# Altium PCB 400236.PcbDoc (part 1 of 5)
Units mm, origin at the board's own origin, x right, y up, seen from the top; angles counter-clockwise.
Board outline 136.53 x 63.5 mm, 4 copper layers (Top Layer, Mid-Layer 1, Mid-Layer 2, Bottom Layer), stack 1.505 mm thick; 340 components, 230 nets, 1369 pads, 1292 vias.
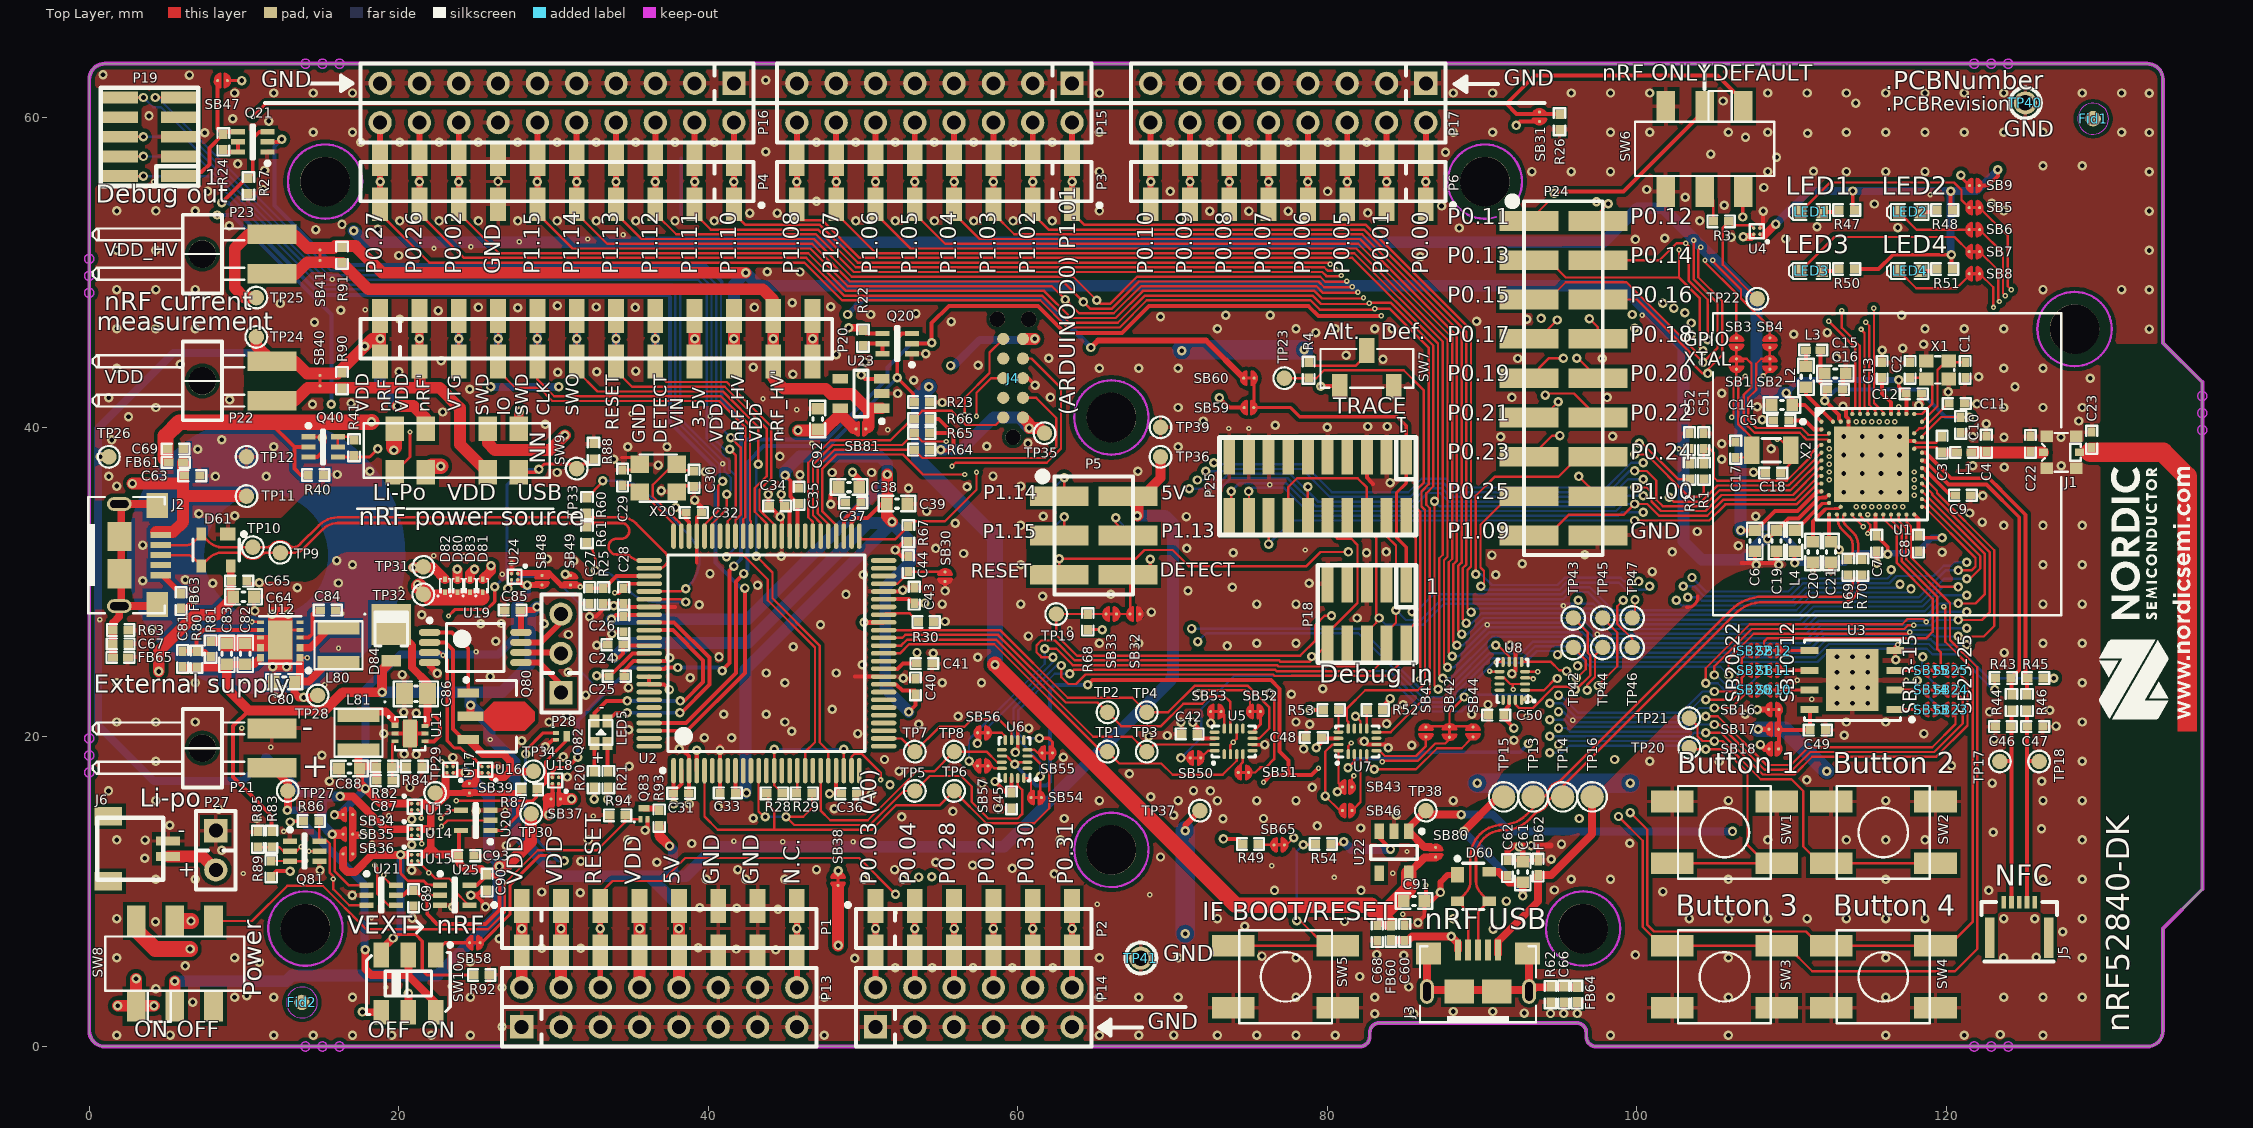
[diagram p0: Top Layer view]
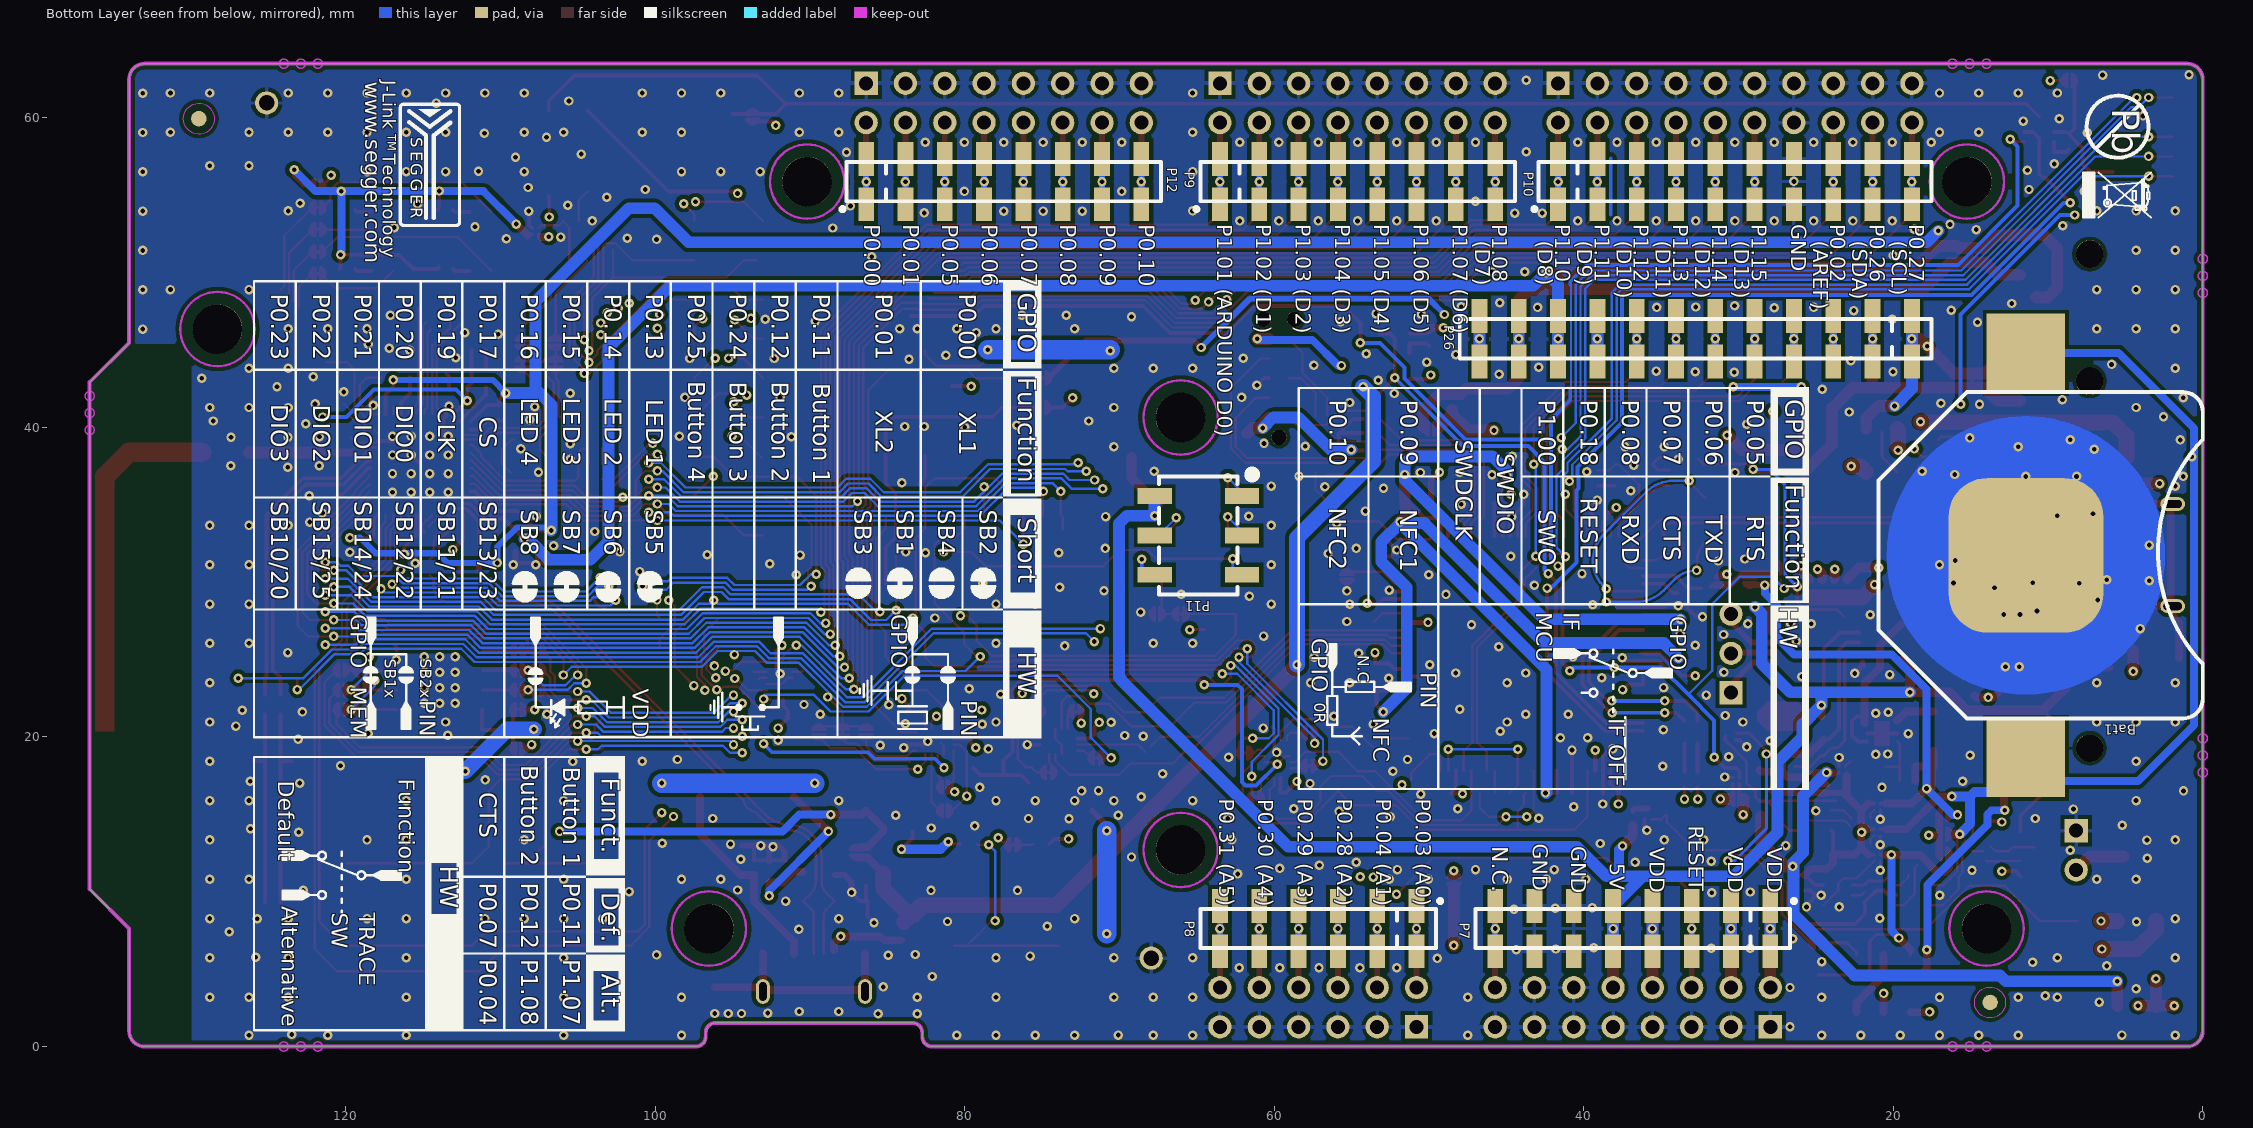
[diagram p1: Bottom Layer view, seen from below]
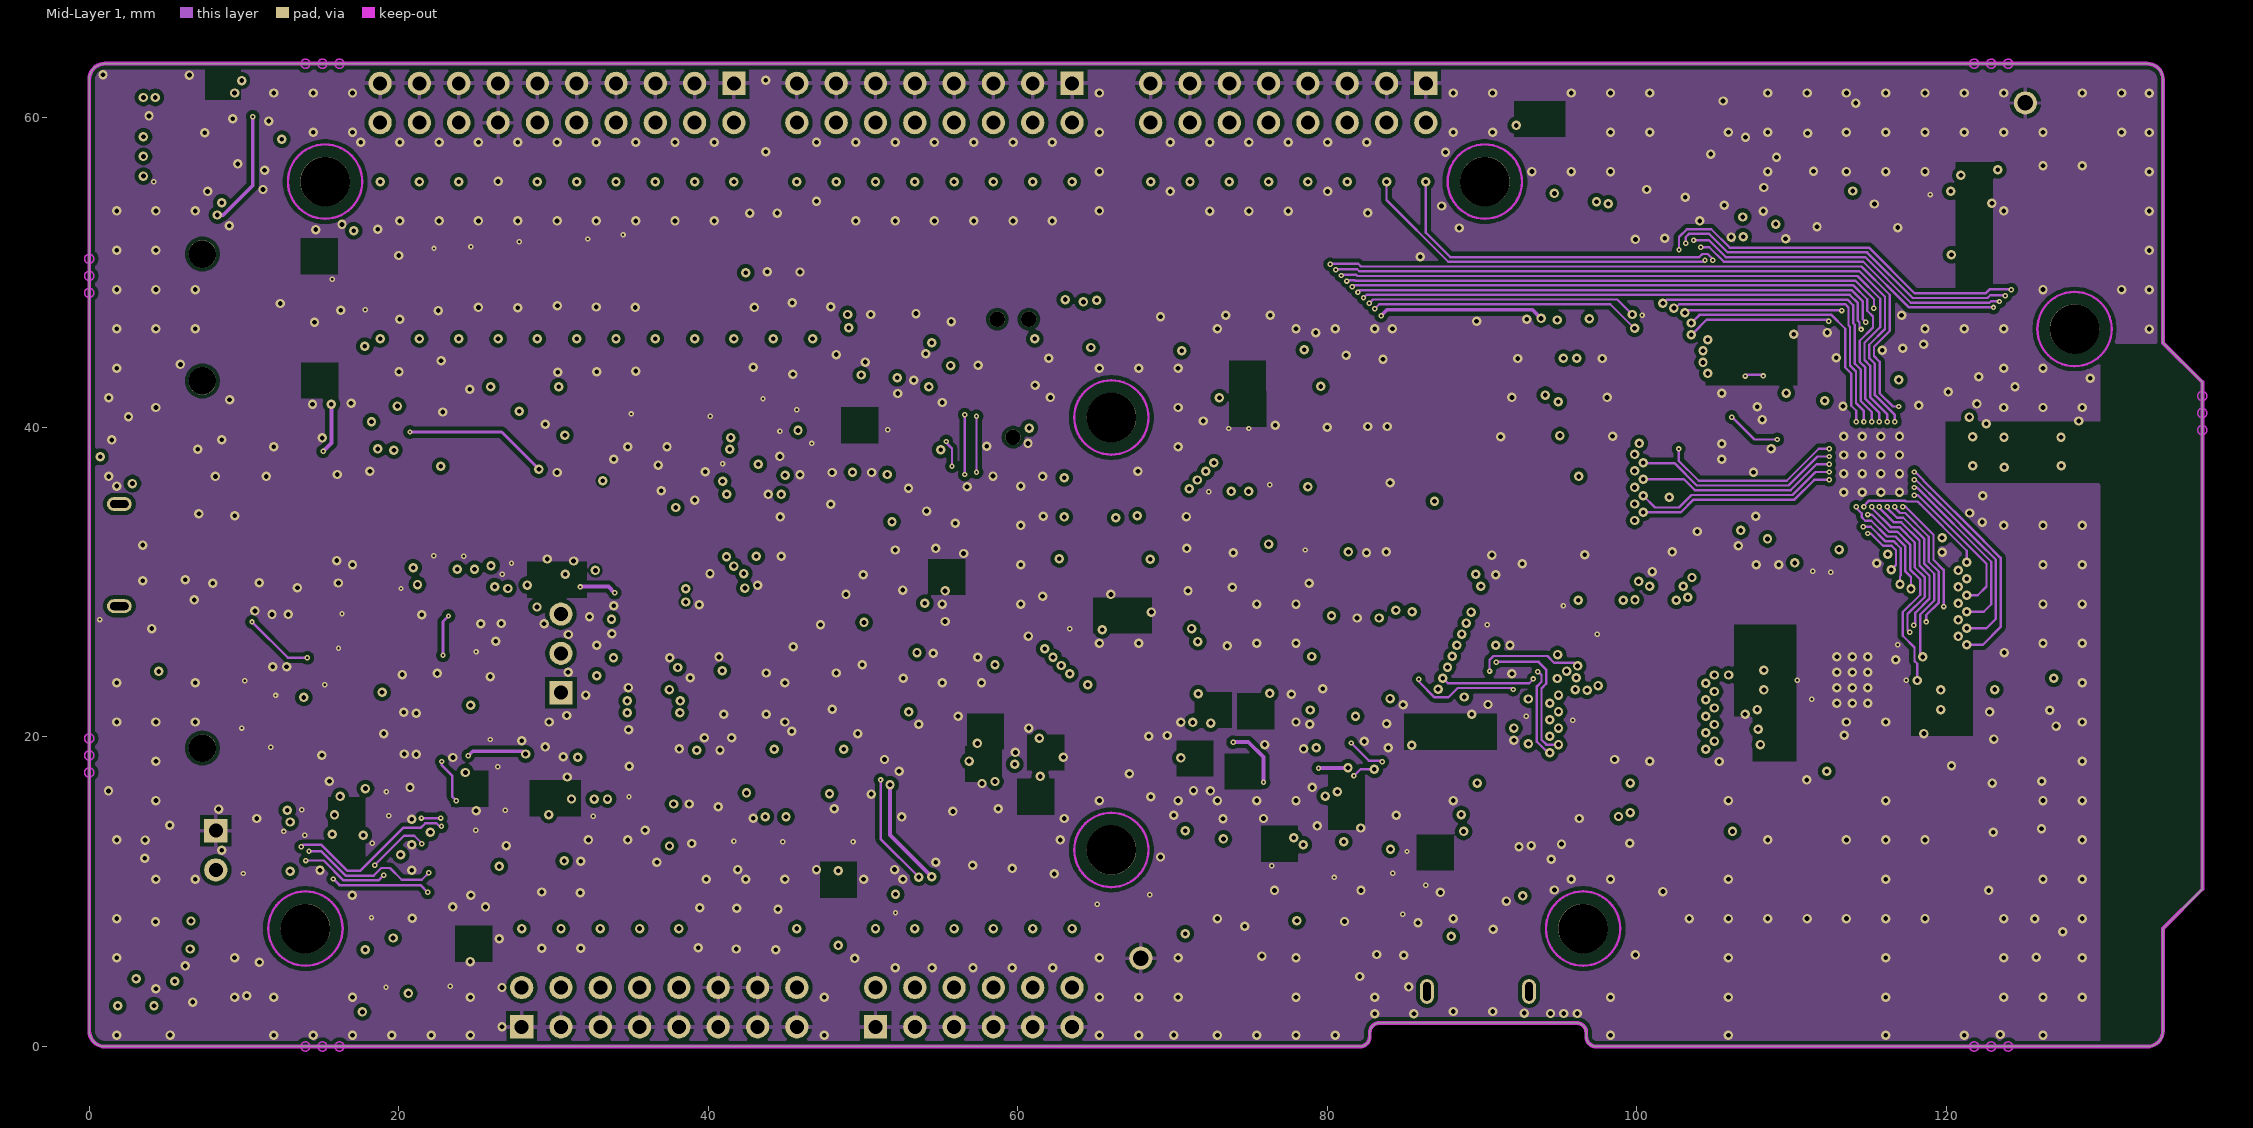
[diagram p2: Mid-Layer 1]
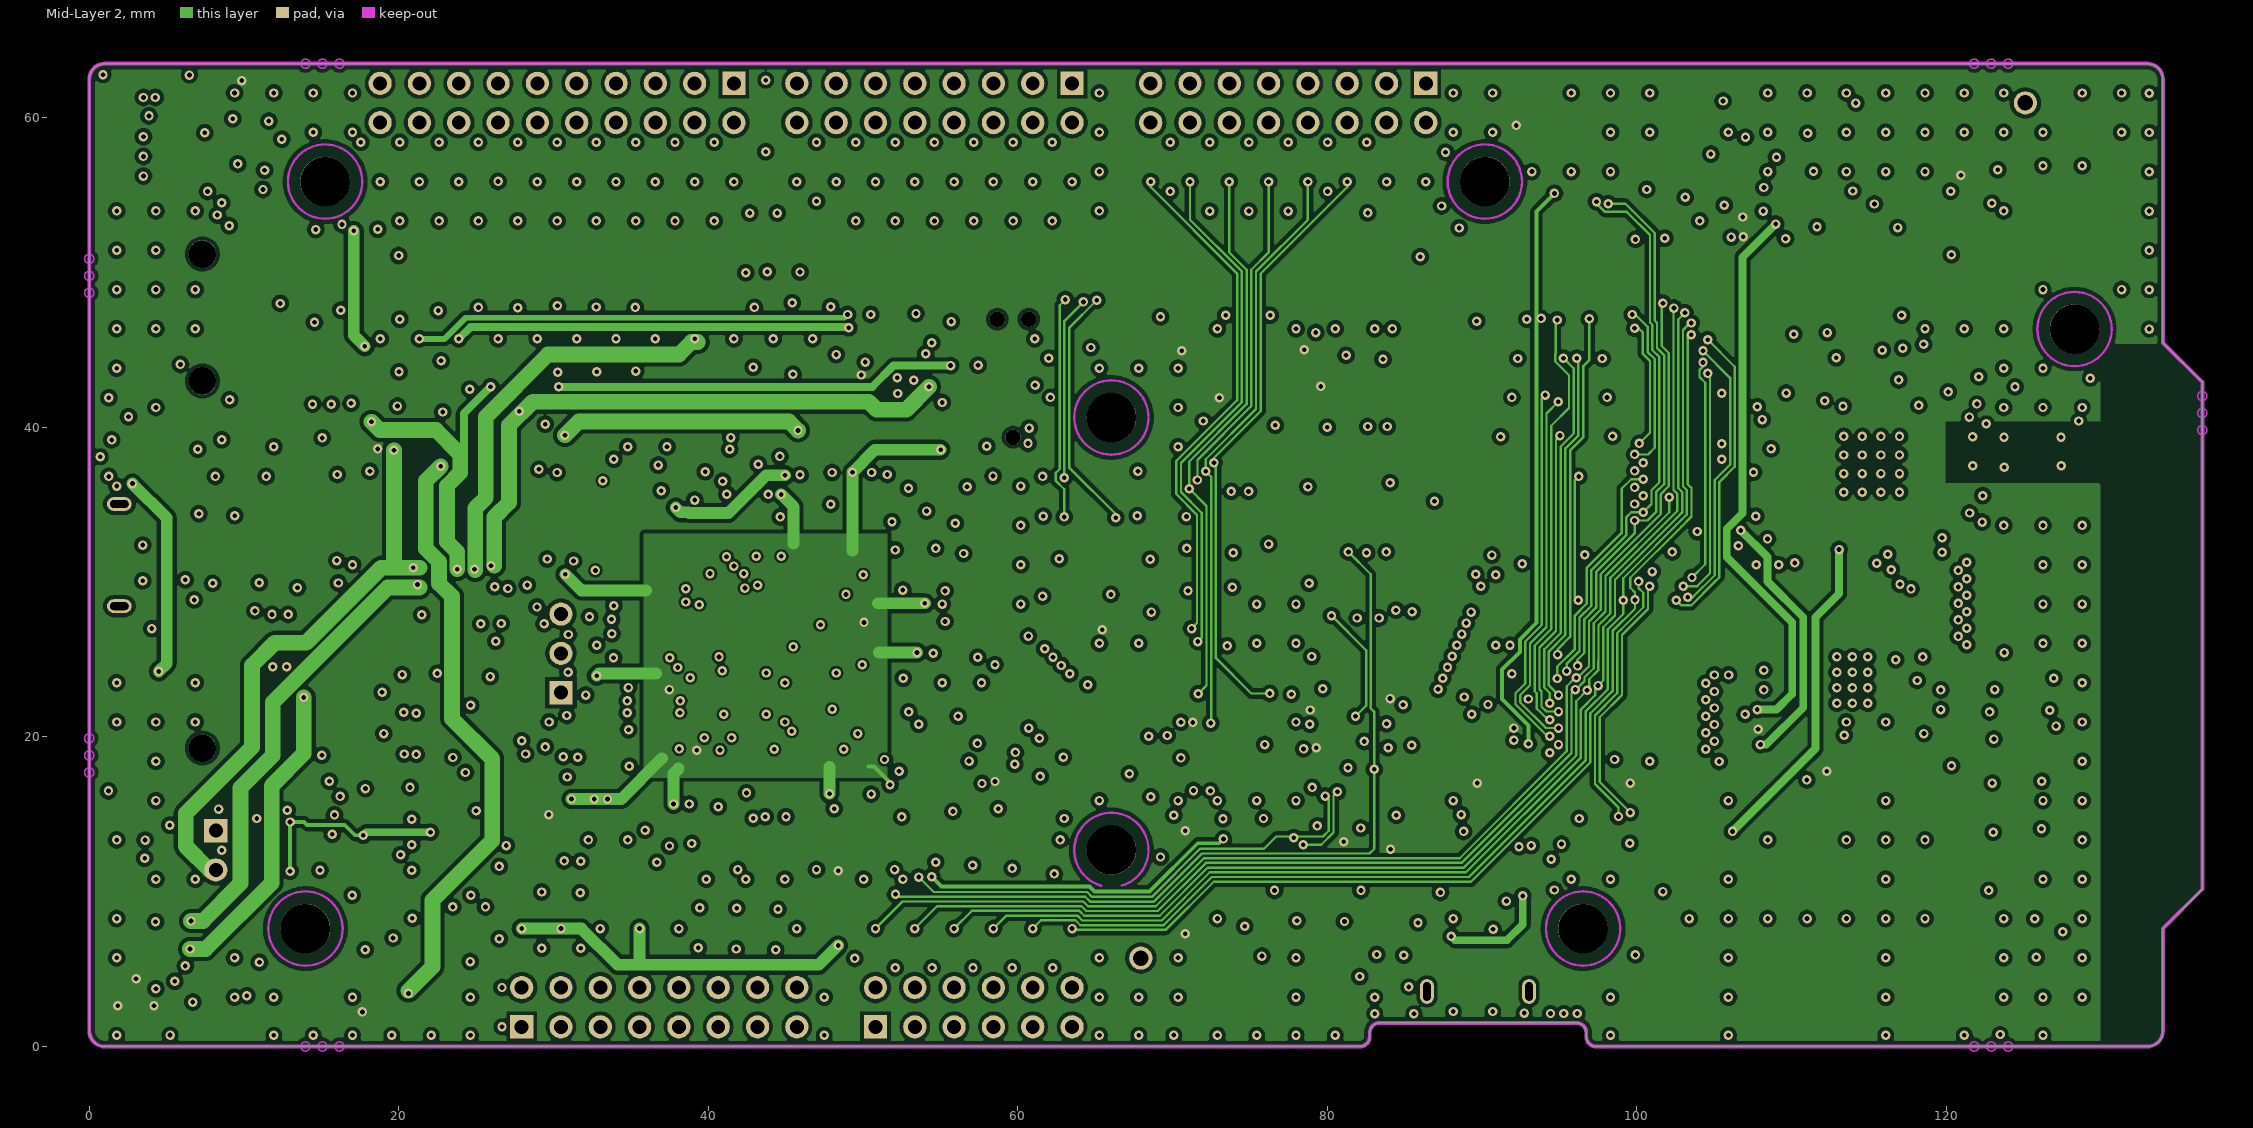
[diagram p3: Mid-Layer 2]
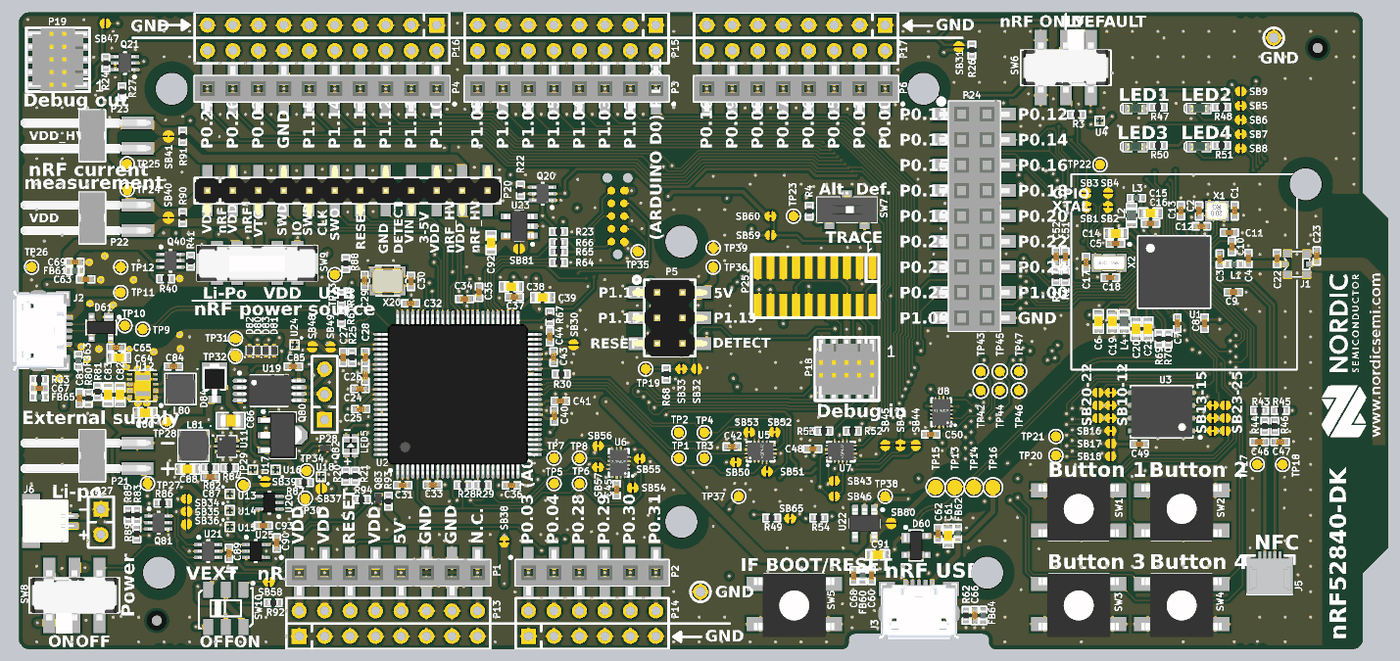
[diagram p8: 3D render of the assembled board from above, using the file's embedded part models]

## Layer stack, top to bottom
Top Solder: solder mask 0.0475, Solder Resist, Dk 3.5
Top Layer: signal copper 0.0175
Dielectric1: prepreg 0.1, FR-4, Dk 3.72
Mid-Layer 1: signal copper 0.035
Dielectric2: core 1.2, FR-4, Dk 3.72
Mid-Layer 2: signal copper 0.035
Dielectric3: prepreg 0.1, FR-4, Dk 3.72
Bottom Layer: signal copper 0.0175
Bottom Solder: solder mask 0.0475, Solder Resist, Dk 3.5

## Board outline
1.016,0 82.099,0 ccw(c82.099,0.635) 82.734,0.635 82.734,0.889 cw(c83.369,0.889) 83.369,1.524 96.09,1.524 cw(c96.09,0.889) 96.725,0.889 96.725,0.635 ccw(c97.36,0.635) 97.36,0 132.969,0 ccw(c132.969,1.016) 133.985,1.016 133.985,7.62 136.525,10.16 136.525,42.926 133.985,45.466 133.985,62.484 ccw(c132.969,62.484) 132.969,63.5 1.016,63.5 ccw(c1.016,62.484) 0,62.484 0,1.016 ccw(c1.016,1.016)

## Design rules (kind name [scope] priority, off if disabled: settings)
Clearance USB_Poly_Clearance [InNamedPolygon('Top_Layer-GND') vs InDifferentialPair('D') or InDifferentialPair('D*')] p1: gap=1.778 ignorepadtopadclearanceinfootprint=FALSE
Clearance "NPTH clearance" [Not PadIsPlated And HoleSize > 0] p2: gap=0.229 ignorepadtopadclearanceinfootprint=FALSE except(0: Arc-Hole Track-Hole SMDPad-Hole THPad-Hole Via-Hole Fill-Hole Poly-Hole Region-Hole Text-Hole)
Clearance USB_Clearance [(InDifferentialPairClass('All Differential Pairs'))] p3: gap=0.152 ignorepadtopadclearanceinfootprint=FALSE except(0: Arc-Hole Track-Hole SMDPad-Hole THPad-Hole Via-Hole Fill-Hole Poly-Hole Region-Hole Text-Hole)
Clearance ANT_Clerance [InNet('ANT')] p4: gap=0.2 ignorepadtopadclearanceinfootprint=FALSE
Clearance Polygon_Clearance [(InNamedPolygon('Top_Layer-GND')) or (InNamedPolygon('Bottom_Layer-GND')) or (InNamedPolygon('Mid_Layer_1-GND')) or (InNamedPolygon('Mid_Layer_2-VDD'))] p5: gap=0.254 ignorepadtopadclearanceinfootprint=FALSE except(0: Arc-Hole Track-Hole SMDPad-Hole THPad-Hole Via-Hole Fill-Hole Poly-Hole Region-Hole Text-Hole)
Clearance SB_Clearance [HasFootprint('Solderbridge') or HasFootprint('QFN40P180X140X55-10N')] p6: gap=0.127 ignorepadtopadclearanceinfootprint=FALSE except(0: Arc-Hole Track-Hole SMDPad-Hole THPad-Hole Via-Hole Fill-Hole Poly-Hole Region-Hole Text-Hole)
Clearance CSP_Clearance [HasFootprint('BGA4C40P2X2_76X76X62')] p7: gap=0.127 ignorepadtopadclearanceinfootprint=FALSE except(0: Arc-Hole Track-Hole SMDPad-Hole THPad-Hole Via-Hole Fill-Hole Poly-Hole Region-Hole Text-Hole)
Clearance P23_Clearance [HasFootprint('FPC_05P-0.5mm-RA-SMD')] p8: gap=0.127 ignorepadtopadclearanceinfootprint=FALSE except(0: Arc-Hole Track-Hole SMDPad-Hole THPad-Hole Via-Hole Fill-Hole Poly-Hole Region-Hole Text-Hole)
Clearance PSON35P100X50-8N_Clearance [HasFootprint('PSON35P100X50-8N')] p9: gap=0.15 ignorepadtopadclearanceinfootprint=FALSE except(0: Arc-Hole Track-Hole SMDPad-Hole THPad-Hole Via-Hole Fill-Hole Poly-Hole Region-Hole Text-Hole)
Clearance Top_layer_Clearance [All vs OnLayer('Top Layer')] p10: gap=0.145 ignorepadtopadclearanceinfootprint=FALSE
Clearance [All] p11: gap=0.15 ignorepadtopadclearanceinfootprint=FALSE except(0: Arc-Hole Track-Hole SMDPad-Hole THPad-Hole Via-Hole Fill-Hole Poly-Hole Region-Hole Text-Hole)
ComponentClearance [All] p1 off: gap=0.254 collisioncheckmode=3 verticalgap=0.254 showdistances=FALSE
DiffPairsRouting [All] p1: maxlimit=0.193 minlimit=0.191 mostfreqgap=0.193 toplayer_minwidth=0.165 toplayer_maxwidth=0.165 toplayer_prefwidth=0.165 midlayer1_minwidth=0.165 midlayer1_maxwidth=0.165 midlayer1_prefwidth=0.165 midlayer2_minwidth=0.165 midlayer2_maxwidth=0.165 midlayer2_prefwidth=0.165 bottomlayer_minwidth=0.165 bottomlayer_maxwidth=0.165 bottomlayer_prefwidth=0.165 maxuncoupledlength=12.7
FabricationTestPointUsage TestPointUsage [All] p1: valid=0 allowmultiple=FALSE
FabricationTestpoint Testpoint [All] p1: side=3 testpointundercomponent=TRUE minsize=1.016 maxsize=2.54 preferedsize=1.524 minholesize=0 maxholesize=1.016 preferedholesize=0.813 testpointgrid=0.025 allowsidetop=TRUE allowsidebottom=TRUE usegrid=TRUE gridtolerance=0
Height [All] p1 off: minheight=0 maxheight=25.4 prefheight=12.7
HoleSize [All] p1: absolutevalues=TRUE maxlimit=5 minlimit=0.15 maxpercent=80.000 minpercent=20.000
MinimumAnnularRing [All] p1 off: minimumring=0.152
NetAntennae NetAntennae_ANT [InNet('ANT')] p1: netantennaetolerance=40
NetAntennae [All] p2: netantennaetolerance=0
PolygonConnect PolygonConnect_1 [isVia and innet(gnd) or isVia and innet('VDD') or HasFootprint('COAXIAL-SWF') or isVia and innet('VDD_SAM')] p1: connectstyle=Direct reliefconductorwidth=0.254 reliefentries=4 polygonreliefangle="90 Angle" airgapwidth=0.254
PolygonConnect [All] p2: connectstyle=Relief reliefconductorwidth=0.254 reliefentries=4 polygonreliefangle="90 Angle" airgapwidth=0.254
RoutingVias [All] p1: holewidth=0.305 width=0.61 viastyle="Through Hole" minholewidth=0.15 minwidth=0.35 maxholewidth=0.305 maxwidth=0.61
SilkToSolderMaskClearance SilkscreenOverComponentPads [IsPad] p1: minsilkscreentomaskgap=0.254 clearancetoexposedcopper=TRUE
SolderMaskExpansion [All] p1: expansion=0.076
UnpouredPolygon [All] p1 off:
Width Width_Diff [(InDifferentialPairClass('All Differential Pairs'))] p1: maxlimit=0.165 minlimit=0.165 preferedwidth=0.165
Width [All] p2: maxlimit=10.16 minlimit=0.145 preferedwidth=0.152 midlayer1_minwidth=0.152 midlayer2_minwidth=0.152 bottomlayer_minwidth=0.152 minimp=50.000000 maximp=50.000000 favimp=50.000000
21 further rules are at their usual default settings.

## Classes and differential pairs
differential pair D: +D_P -D_N
differential pair D*: +D*_P -D*_N
differential pair DHSD: +DHSD_P -DHSD_N
differential pair DFSD: +DFSD_P -DFSD_N

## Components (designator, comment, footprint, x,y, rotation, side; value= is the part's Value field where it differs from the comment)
Bat1 "Bat Holder CR2032" CR2032_HOLDER_SMD 11.43,31.735 r270 bottom locked
C1 "12pF" CAPC1005X04L 121.203,43.713 r270 top
C2 "12pF" CAPC1005X04L 117.647,43.713 r90 top
C3 "1.0pF" CAPC1005X04L 119.715,38.893 r270 top
C4 "1.0pF" CAPC1005X04L 122.57,38.938 r270 top
C5 "100nF" CAPC1005X04L 109.324,40.455 r180 top
C6 "4.7µF" CAPC1608X06L 107.613,32.667 r270 top
C7 "100nF" CAPC1005X04L 115.49,32.492 r270 top
C8 "100nF" CAPC1005X04L 118.189,32.492 r270 top
C9 "820pF" CAPC1005X04L 121.064,35.617 r0 top
C10 "N.C." CAPC1005X04L 120.919,40.157 r90 top
C11 "100pF" CAPC1005X04L 120.664,41.542 r0 top
C12 "100nF" CAPC1005X04L 117.889,42.167 r0 top
C13 "N.C." CAPC1005X04L 115.839,43.717 r90 top
C14 "1.0µF" CAPC1608X06L 109.364,41.444 r180 top
C15 "1.0µF" CAPC1608X06L 112.814,43.481 r180 top
C16 "47nF" CAPC1005X04L 112.801,42.443 r0 top
C17 "12pF" CAPC1005X04L 106.385,38.55 r270 top
C18 "12pF" CAPC1005X04L 108.798,37.052 r0 top
C19 "4.7µF" CAPC1608X06L 109.014,32.667 r270 top
C20 "4.7µF" CAPC1608X06L 111.364,31.942 r270 top
C21 "4.7µF" CAPC1608X06L 112.539,31.942 r270 top
C22 "N.C." CAPC1005X04L 125.423,38.935 r90 top
C23 "1.2pF" CAPC1005X04L 129.379,39.204 r90 top
C24 "100nF" CAPC1005X04L 34.001,25.959 r0 top
C25 "100nF" CAPC1005X04L 34.077,23.927 r180 top
C26 "100nF" CAPC1005X04L 34.534,27.28 r90 top
C27 "10pF" CAPC1005X04L 32.324,29.108 r90 top
C28 "100nF" CAPC1005X04L 34.534,29.108 r90 top
C29 "18pF" CAPC1005X04L 34.458,36.754 r90 top
C30 "18pF" CAPC1005X04L 39.081,36.678 r270 top
C31 "100nF" CAPC1005X04L 38.242,16.358 r180 top
C32 "100nF" CAPC1005X04L 39.055,34.493 r0 top
C33 "100nF" CAPC1005X04L 41.25,16.383 r0 top
C34 "100nF" CAPC1005X04L 44.44,34.925 r0 top
C35 "100nF" CAPC1005X04L 45.862,35.585 r270 top
C36 "100nF" CAPC1005X04L 49.098,16.332 r180 top
C37 "100nF" CAPC1005X04L 49.368,35.128 r0 top
C38 "10µF" CAPC1608X06L 49.088,36.144 r0 top
C39 "10µF" CAPC1608X06L 52.197,35.077 r180 top
C40 "100nF" CAPC1005X04L 53.381,23.266 r270 top
C41 "100nF" CAPC1005X04L 53.965,24.74 r180 top
C42 "100nF" CAPC1005X04L 71.095,20.193 r0 top
C43 "100nF" CAPC1005X04L 53.305,29.134 r270 top
C44 "10nF" CAPC1005X04L 52.924,31.166 r270 top
C45 "100nF" CAPC1005X04L 59.588,15.9 r90 top
C46 "300pF" CAPC1005X04L 123.647,20.669 r180 top
C47 "300pF" CAPC1005X04L 125.73,20.669 r180 top
C48 "100nF" CAPC1005X04L 79.121,19.964 r0 top
C49 "100nF" CAPC1005X04L 111.684,20.447 r180 top
C50 "100nF" CAPC1005X04L 90.907,21.412 r0 top
C51 "N.C." CAPC1005X04L 104.318,39.116 r270 top
C52 "N.C." CAPC1005X04L 103.403,39.116 r90 top
C60 "10nF" CAPC1005X04L 84.995,7.341 r270 top
C61 "10µF" CAPC1608X06L 92.623,11.278 r270 top
C62 "100nF" CAPC1005X04L 91.632,11.532 r270 top
C63 "10nF" CAPC1005X04L 6.655,36.881 r0 top
C64 "10µF" CAPC1608X06L 9.972,29.058 r180 top
C65 "100nF" CAPC1005X04L 9.693,30.074 r180 top
C66 "100nF" CAPC1005X04L 95.282,3.355 r90 top
C67 "100nF" CAPC1005X04L 2.028,26.01 r180 top
C68 "100nF" CAPC1005X04L 83.223,7.328 r90 top
C69 "100nF" CAPC1005X04L 5.578,38.6 r180 top
C80 "10µF" CAPC1608X06L 12.598,23.571 r0 top
C81 "15pF" CAPC1005X04L 6.045,25.044 r270 top
C82 "10µF" CAPC1608X06L 10.084,25.375 r270 top
C83 "10µF" CAPC1608X06L 8.89,25.375 r270 top
C84 "470nF" CAPC1005X04L 15.418,28.194 r180 top
C85 "100nF" CAPC1005X04L 27.356,28.194 r0 top
C86 "4.7µF" CAPC2012X11L 21.107,22.784 r0 top
C87 "150pF" CAPC1005X04L 19.075,17.17 r180 top
C88 "10µF" CAPC1608X06L 16.815,17.958 r0 top
C89 "100nF" CAPC1005X04L 20.955,9.576 r90 top
C90 "100nF" CAPC1005X04L 25.705,10.592 r90 top
C91 "1.0µF" CAPC1608X06L 85.598,9.398 r180 top
C92 "1.0µF" CAPC1608X06L 47.066,40.538 r270 top
C93 "100nF" CAPC1005X04L 24.359,12.319 r180 top
D60 "PRTR5V0U2X" SOT190P230X110-4L 89.427,10.34 r0 top
D61 "PRTR5V0U2X" SOT190P230X110-4L 8.194,32.08 r270 top
D80 "NSR0620P2T5G" SODFL100X40-2N 23.8,29.766 r90 top
D81 "NSR0620P2T5G" SODFL100X40-2N 25.425,29.766 r90 top
D82 "NSR0620P2T5G" SODFL100X40-2N 22.987,29.766 r90 top
D83 "NSR0620P2T5G" SODFL100X40-2N 24.613,29.766 r90 top
D84 "MBRM110E" DO-216AA 19.507,26.568 r270 top
FB60 "120R/0.55A" INDC1005X04L 84.106,7.341 r90 top
FB61 "120R/0.55A" INDC1005X04L 5.585,37.734 r180 top
FB62 "120R/0.55A" INDC1005X04L 93.614,11.558 r90 top
FB63 "120R/0.55A" INDC1005X04L 5.933,28.779 r270 top
FB64 "120R/0.55A" INDC1005X04L 96.12,3.355 r270 top
FB65 "120R/0.55A" INDC1005X04L 2.021,25.139 r0 top
Fid1 "Fiducial mark" Fiducial 129.471,59.944 r180 top
Fid2 "Fiducial mark" Fiducial 13.743,2.845 r0 top
J1 "MM8130-2600" COAXIAL-SWF 127.423,38.391 r90 top
J2 "MicroUSB-B" USB-Micro-B-RA-SMD-PiP 4.619,31.75 r0 top
J3 "MicroUSB-B" USB-Micro-B-RA-SMD-PiP 89.729,6.232 r90 top
J4 "TC2050-IDC" TC2050-IDC-NLFP 59.69,43.18 r90 top
J5 "FPC 0.5mm RA SMD" FPC_05P-0.5mm-RA-SMD 123.698,9.328 r0 top
J6 "HDR-2, 1mm" SM02B-SRSS-TB 5.105,12.776 r270 top
L1 "3.9nH" INDC1005X04L 121.138,38.385 r0 top
L2 "10µH" INDC1608X06L 110.914,43.267 r270 top
L3 "15nH" INDC1005X04L 111.389,44.992 r180 top
L4 "10µH" INDC1608X06L 110.189,32.667 r90 top
L80 "2.2µH" TY-NR3015 16.104,25.933 r270 top
L81 "4.7µH" TY-NR3015 17.399,20.269 r270 top
LED1 "L0603G" LED_0603_G 111.273,53.917 r0 top
LED2 "L0603G" LED_0603_G 117.623,53.917 r0 top
LED3 "L0603G" LED_0603_G 111.273,50.107 r0 top
LED4 "L0603G" LED_0603_G 117.623,50.107 r0 top
LED5 "LED RG" LED_DUAL_0606 33.061,20.295 r180 top
P1 "Socket 1x8" SOCKET_1x8_SMD 27.94,7.62 r0 top locked
P2 "Socket 1x6" SOCKET_1x6_SMD 50.8,7.62 r0 top locked
P3 "Socket 1x8" SOCKET_1x8_SMD 63.5,55.88 r180 top locked
P4 "Socket 1x10" SOCKET_1x10_SMD 41.656,55.88 r180 top locked
P5 "Pin Hdr 2x3" HDR_2x3-SMD 64.897,33.02 r270 top locked
P6 "Socket 1x8" SOCKET_1x8_SMD 86.36,55.88 r180 top locked
P7 "Pin List 1x8" LIST_1x8_SMD-NC 27.94,7.62 r0 bottom locked
P8 "Pin List 1x6" LIST_1x6_SMD-NC 50.8,7.62 r0 bottom locked
P9 "Pin List 1x8" LIST_1x8_SMD-NC 63.5,55.88 r180 bottom locked
P10 "Pin List 1x10" LIST_1x10_SMD-NC 41.656,55.88 r180 bottom locked
P11 "Socket 2x3" SOCKET_2x3_SMD-2.54mm-bottom-NC 64.897,33.02 r270 top locked
P12 "Pin List 1x8" LIST_1x8_SMD-NC 86.36,55.88 r180 bottom locked
P13 "Pin Header 2x8" HDR_2x8-NC 36.83,2.54 r0 top locked
P14 "Pin Header 2x6" HDR_2x6-NC 57.15,2.54 r0 top locked
P15 "Pin Header 2x8" HDR_2x8-NC 54.61,60.96 r180 top locked
P16 "Pin Header 2x10" HDR_2x10-NC 30.226,60.96 r180 top locked
P17 "Pin Header 2x8" HDR_2x8-NC 77.47,60.96 r180 top locked
P18 "Pin Header 2x5, 1.27mm" HDR_2x5-SMD-1.27mm-K 82.55,27.94 r180 top locked
P19 "Pin Header 2x5, 1.27mm" HDR_2x5-SMD-1.27mm-K 3.886,58.776 r90 top
P20 "Pin List 1x12" LIST_1x12_SMD 18.796,45.72 r0 top locked
P21 "Pin List 1x2, Angled" LIST_ANG_1x2-SMD-2.54MM 11.811,19.279 r270 top
P22 "Pin List 1x2, Angled" LIST_ANG_1x2-SMD-2.54MM 11.811,43 r270 top
P23 "Pin List 1x2, Angled" LIST_ANG_1x2-SMD-2.54MM 11.811,51.2 r270 top
P24 "Socket 2x9" SOCKET_2x9_SMD-2.54mm 95.25,43.18 r270 top locked
P25 "Pin Header 2x10, 1.27mm" HDR_2x10-SMD-1.27mm-NC 79.375,36.195 r180 top locked
P26 "Socket 1x12" LIST_1x12_SMD-NC 18.796,45.72 r0 bottom locked
P27 "Pin List 1x2" LIST_1x2-NC 8.179,12.675 r270 top locked
P28 "Pin List 1x3" LIST_1x3-NC 30.48,25.4 r90 top locked
Q20 "FDG6321C" SOT65P210X100-6N 52.205,45.415 r180 top
Q21 "FDG6321C" SOT65P210X100-6N 10.566,58.445 r180 top
Q40 "FDG6321C" SOT65P210X100-6N 15.113,38.735 r0 top
Q80 "FCX690BTA" SOT89-150P409X160-3N 26.289,21.336 r0 top
Q81 "FDG6303N" SOT65P210X100-6N 13.919,12.624 r0 top
Q82 "RV2C010UNT2L" DFN65P100X40-3L 30.505,20.041 r0 top
Q83 "RV2C010UNT2L" DFN65P100X40-3L 35.839,15.037 r90 top
R1 "0R" RESC1005X04L 104.318,37.16 r90 top
R2 "0R" RESC1005X04L 103.403,37.16 r90 top
R3 "10k" RESC1005X04L 105.435,53.315 r180 top
R4 "10k" RESC1005X04L 78.791,43.688 r90 top
R20 "220R" RESC1005X04L 32.585,17.247 r270 top
R21 "220R" RESC1005X04L 33.537,17.247 r270 top
R22 "10k" RESC1005X04L 49.996,45.771 r270 top
R23 "10k" RESC1005X04L 53.797,41.631 r180 top
R24 "10k" RESC1005X04L 8.661,58.445 r270 top
R25 "6k8" RESC1005X04L 33.213,29.108 r90 top
R26 "47k" RESC1005X04L 94.996,59.741 r270 top
R27 "10k" RESC1005X04L 10.287,55.601 r90 top
R28 "150R" RESC1005X04L 44.272,16.358 r180 top
R29 "150R" RESC1005X04L 46.203,16.358 r0 top
R30 "0R" RESC1005X04L 54.067,27.432 r180 top
R40 "150k" RESC1005X04L 14.63,36.932 r0 top
R41 "1M0" RESC1005X04L 17.12,38.684 r90 top
R43 "N.C." RESC1005X04L 123.669,23.8 r0 top
R44 "0R" RESC1005X04L 124.206,22.225 r90 top
R45 "N.C." RESC1005X04L 125.751,23.8 r180 top
R46 "0R" RESC1005X04L 125.197,22.225 r90 top
R47 "220R" RESC1005X04L 113.559,54.044 r0 top
R48 "220R" RESC1005X04L 119.884,54.044 r0 top
R49 "10k" RESC1005X04L 75.032,13.081 r180 top
R50 "220R" RESC1005X04L 113.559,50.234 r0 top
R51 "220R" RESC1005X04L 119.884,50.234 r0 top
R52 "4k7" RESC1005X04L 83.083,21.742 r180 top
R53 "4k7" RESC1005X04L 80.239,21.742 r0 top
R54 "N.C." RESC1005X04L 79.731,13.081 r0 top
R60 "39R" RESC1005X04L 32.157,34.949 r270 top
R61 "39R" RESC1005X04L 32.157,33.063 r90 top
R62 "10k" RESC1005X04L 94.418,3.355 r90 top
R63 "10k" RESC1005X04L 2.028,26.899 r180 top
R64 "4k7" RESC1005X04L 53.797,38.557 r0 top
R65 "4k7" RESC1005X04L 53.797,39.624 r0 top
R66 "4k7" RESC1005X04L 53.797,40.538 r0 top
R67 "4k7" RESC1005X04L 52.924,33.122 r270 top
R68 "1M0" RESC1005X04L 64.516,27.432 r270 top
R69 "0R" RESC1005X04L 113.65,30.958 r270 top
R70 "0R" RESC1005X04L 114.565,30.958 r270 top
R80 "270k" RESC1005X04L 6.934,25.019 r270 top
R81 "30k" RESC1005X04L 7.849,25.679 r270 top
R82 "330k" RESC1005X04L 19.05,18.085 r180 top
R83 "820k" RESC1005X04L 11.782,13.386 r270 top
R84 "120k" RESC1005X04L 21.006,18.085 r180 top
R85 "470k" RESC1005X04L 10.893,13.386 r90 top
R86 "1M0" RESC1005X04L 14.351,14.554 r0 top
R87 "1M0" RESC1005X04L 28.448,16.612 r0 top
R88 "N.C." RESC1005X04L 32.588,38.456 r90 top
R89 "1M0" RESC1005X04L 11.76,11.481 r90 top
R90 "N.C." RESC1005X04L 16.332,43.025 r90 top
R91 "N.C." RESC1005X04L 16.332,51.13 r90 top
R92 "10M" RESC1005X04L 25.349,4.623 r0 top
R93 "1k" RESC1005X04L 36.83,14.757 r90 top
R94 "10M" RESC1005X04L 34.138,14.935 r180 top
SB1 "Solderbridge" Solderbridge_Shorted#1 106.426,44.094 r90 top net-tie
SB2 "Solderbridge" Solderbridge_Shorted#1 108.585,44.094 r90 top net-tie
SB3 "Solderbridge" Solderbridge#1 106.426,45.466 r90 top
SB4 "Solderbridge" Solderbridge#2 108.585,45.466 r90 top
SB5 "Solderbridge" Solderbridge_Shorted#1 121.801,54.197 r180 top net-tie
SB6 "Solderbridge" Solderbridge_Shorted#1 121.801,52.774 r180 top net-tie
SB7 "Solderbridge" Solderbridge_Shorted#1 121.801,51.352 r180 top net-tie
SB8 "Solderbridge" Solderbridge_Shorted#1 121.801,49.93 r180 top net-tie
SB9 "Solderbridge" Solderbridge#3 121.802,55.619 r0 top
SB10 "Solderbridge" Solderbridge_Shorted#1 108.839,23.038 r0 top net-tie
SB11 "Solderbridge" Solderbridge_Shorted#1 108.839,24.308 r0 top net-tie
SB12 "Solderbridge" Solderbridge_Shorted#1 108.839,25.578 r0 top net-tie
SB13 "Solderbridge" Solderbridge_Shorted#1 118.999,21.768 r180 top net-tie
SB14 "Solderbridge" Solderbridge_Shorted#1 118.999,23.038 r180 top net-tie
SB15 "Solderbridge" Solderbridge_Shorted#1 118.999,24.308 r180 top net-tie
SB16 "Solderbridge" Solderbridge_Shorted#1 108.839,21.768 r0 top net-tie
SB17 "Solderbridge" Solderbridge#3 108.839,20.498 r0 top
SB18 "Solderbridge" Solderbridge#3 108.839,19.228 r0 top
SB20 "Solderbridge" Solderbridge#2 107.569,23.038 r180 top
SB21 "Solderbridge" Solderbridge#3 107.569,24.308 r180 top
SB22 "Solderbridge" Solderbridge#2 107.569,25.578 r180 top
SB23 "Solderbridge" Solderbridge#2 120.269,21.768 r0 top
SB24 "Solderbridge" Solderbridge#2 120.269,23.038 r0 top
SB25 "Solderbridge" Solderbridge#3 120.269,24.308 r0 top
SB30 "Solderbridge" Solderbridge#2 55.297,30.353 r270 top
SB31 "Solderbridge" Solderbridge#2 93.701,60.071 r90 top
SB32 "Solderbridge" Solderbridge#2 67.564,27.94 r180 top
SB33 "Solderbridge" Solderbridge_Shorted#1 66.04,27.94 r180 top net-tie
SB34 "Solderbridge" Solderbridge#2 16.716,14.986 r180 top
SB35 "Solderbridge" Solderbridge#2 16.713,13.716 r180 top
SB36 "Solderbridge" Solderbridge#2 16.716,12.446 r180 top
SB37 "Solderbridge" Solderbridge#2 30.144,15.992 r180 top
SB38 "Solderbridge" Solderbridge_Shorted#1 48.387,10.744 r90 top net-tie
SB39 "Solderbridge" Solderbridge#4 24.562,16.688 r270 top
SB40 "Solderbridge" Solderbridge_Shorted#1 14.91,43.025 r270 top net-tie
SB41 "Solderbridge" Solderbridge_Shorted#1 14.91,51.13 r270 top net-tie
SB42 "Solderbridge" Solderbridge_Shorted#1 87.884,20.32 r90 top net-tie
SB43 "Solderbridge" Solderbridge#2 81.28,16.764 r0 top
SB44 "Solderbridge" Solderbridge#1 89.408,20.32 r90 top
SB45 "Solderbridge" Solderbridge#3 86.36,20.32 r90 top
SB46 "Solderbridge" Solderbridge#2 81.28,15.24 r180 top
SB47 "Solderbridge" Solderbridge#2 8.611,62.408 r180 top
SB48 "Solderbridge" Solderbridge#2 29.261,30.124 r270 top
SB49 "Solderbridge" Solderbridge#2 31.09,30.124 r270 top
SB50 "Solderbridge" Solderbridge_Shorted#2 71.476,18.644 r0 top net-tie
SB51 "Solderbridge" Solderbridge_Shorted#2 74.574,17.704 r180 top net-tie
SB52 "Solderbridge" Solderbridge_Shorted#2 75.336,21.641 r0 top net-tie
SB53 "Solderbridge" Solderbridge_Shorted#2 72.796,21.641 r0 top net-tie
SB54 "Solderbridge" Solderbridge_Shorted#2 61.189,16.078 r180 top net-tie
SB55 "Solderbridge" Solderbridge_Shorted#2 61.9,18.974 r180 top net-tie
SB56 "Solderbridge" Solderbridge_Shorted#2 57.734,20.269 r0 top net-tie
SB57 "Solderbridge" Solderbridge_Shorted#2 57.734,18.136 r0 top net-tie
SB58 "Solderbridge" Solderbridge_Shorted#1 24.917,6.706 r180 top net-tie
SB59 "Solderbridge" Solderbridge#4 74.93,41.275 r180 top
SB60 "Solderbridge" Solderbridge_Shorted#1 74.93,43.18 r180 top net-tie
SB65 "Solderbridge" Solderbridge_Shorted#1 76.886,13.03 r180 top net-tie
SB80 "Solderbridge" Solderbridge#1 86.995,12.548 r270 top
SB81 "Solderbridge" Solderbridge#2 49.86,39.903 r180 top
SW1 "PB SW" Switch-PB-6.2x6.3mm-SMD 105.653,13.83 r0 top locked
SW2 "PB SW" Switch-PB-6.2x6.3mm-SMD 115.915,13.83 r0 top locked
SW3 "PB SW" Switch-PB-6.2x6.3mm-SMD 105.653,4.502 r180 top locked
SW4 "PB SW" Switch-PB-6.2x6.3mm-SMD 115.915,4.502 r180 top locked
SW5 "PB SW" Switch-PB-6.2x6.3mm-SMD 77.292,4.502 r180 top
SW6 "MKH-22D14-G2-B" MKH-22D14-G2-B 104.369,57.988 r180 top
SW7 "Switch" CJS-120xA 82.55,43.815 r0 top
SW8 "MKH-22D14-G2-B" MKH-22D14-G2-B 5.528,5.359 r0 top
SW9 "JS203011JCQN" Switch-Slide-J-Lead-DP3T-13x3.5mm 23.749,38.506 r0 top locked
SW10 "CAS-220TA" CAS-220TA 20.625,4.064 r180 top
TP1 "Ø1.0mm,SMD" TP_SMD_Ø1.0mm 65.786,19.05 r90 top
TP2 "Ø1.0mm,SMD" TP_SMD_Ø1.0mm 65.786,21.59 r90 top
TP3 "Ø1.0mm,SMD" TP_SMD_Ø1.0mm 68.326,19.05 r90 top
TP4 "Ø1.0mm,SMD" TP_SMD_Ø1.0mm 68.326,21.59 r90 top
TP5 "Ø1.0mm,SMD" TP_SMD_Ø1.0mm 53.34,16.51 r90 top
TP6 "Ø1.0mm,SMD" TP_SMD_Ø1.0mm 55.88,16.51 r90 top
TP7 "Ø1.0mm,SMD" TP_SMD_Ø1.0mm 53.34,19.05 r90 top
TP8 "Ø1.0mm,SMD" TP_SMD_Ø1.0mm 55.88,19.05 r90 top
TP9 "Ø1.0mm,SMD" TP_SMD_Ø1.0mm 12.344,31.901 r90 top
TP10 "Ø1.0mm,SMD" TP_SMD_Ø1.0mm 10.566,32.259 r90 top
TP11 "Ø1.0mm,SMD" TP_SMD_Ø1.0mm 10.16,35.56 r90 top locked
TP12 "Ø1.0mm,SMD" TP_SMD_Ø1.0mm 10.16,38.1 r90 top locked
TP13 "Ø1.5mm,SMD" TP_SMD_Ø1.5mm 93.294,16.129 r0 top
TP14 "Ø1.5mm,SMD" TP_SMD_Ø1.5mm 95.199,16.129 r0 top
TP15 "Ø1.5mm,SMD" TP_SMD_Ø1.5mm 91.389,16.129 r0 top
TP16 "Ø1.5mm,SMD" TP_SMD_Ø1.5mm 97.104,16.129 r0 top
TP17 "Ø1.0mm,SMD" TP_SMD_Ø1.0mm 123.444,18.415 r90 top
TP18 "Ø1.0mm,SMD" TP_SMD_Ø1.0mm 125.984,18.415 r90 top
TP19 "Ø1.0mm,SMD" TP_SMD_Ø1.0mm 62.484,27.94 r90 top
TP20 "Ø1.0mm,SMD" TP_SMD_Ø1.0mm 103.378,19.304 r0 top
TP21 "Ø1.0mm,SMD" TP_SMD_Ø1.0mm 103.378,21.209 r0 top
TP22 "Ø1.0mm,SMD" TP_SMD_Ø1.0mm 107.772,48.311 r0 top
TP23 "Ø1.0mm,SMD" TP_SMD_Ø1.0mm 77.216,43.18 r0 top
TP24 "Ø1.0mm,SMD" TP_SMD_Ø1.0mm 10.795,45.847 r0 top
TP25 "Ø1.0mm,SMD" TP_SMD_Ø1.0mm 10.795,48.387 r0 top
TP26 "Ø1.0mm,SMD" TP_SMD_Ø1.0mm 1.27,38.1 r0 top
TP27 "Ø1.0mm,SMD" TP_SMD_Ø1.0mm 12.827,16.51 r0 top
TP28 "Ø1.0mm,SMD" TP_SMD_Ø1.0mm 14.757,22.682 r0 top
TP29 "Ø1.0mm,SMD" TP_SMD_Ø1.0mm 22.352,16.383 r0 top
TP30 "Ø1.0mm,SMD" TP_SMD_Ø1.0mm 28.55,15.037 r270 top
TP31 "Ø1.0mm,SMD" TP_SMD_Ø1.0mm 21.59,30.988 r90 top
TP32 "Ø1.0mm,SMD" TP_SMD_Ø1.0mm 21.59,29.21 r0 top
TP33 "Ø1.0mm,SMD" TP_SMD_Ø1.0mm 31.496,37.338 r0 top
TP34 "Ø1.0mm,SMD" TP_SMD_Ø1.0mm 28.702,17.78 r0 top
TP35 "Ø1.0mm,SMD" TP_SMD_Ø1.0mm 61.722,39.624 r0 top
TP36 "Ø1.0mm,SMD" TP_SMD_Ø1.0mm 69.215,38.1 r0 top
TP37 "Ø1.0mm,SMD" TP_SMD_Ø1.0mm 71.755,15.24 r0 top
TP38 "Ø1.0mm,SMD" TP_SMD_Ø1.0mm 86.36,15.24 r0 top
TP39 "Ø1.0mm,SMD" TP_SMD_Ø1.0mm 69.215,40.005 r0 top
TP40 "TP" TESTPAD-TH 125.095,60.96 r0 top
TP41 "TP" TESTPAD-TH 67.945,5.715 r0 top
TP42 "Ø1.0mm,SMD" TP_SMD_Ø1.0mm 95.885,25.781 r0 top
TP43 "Ø1.0mm,SMD" TP_SMD_Ø1.0mm 95.885,27.686 r0 top
TP44 "Ø1.0mm,SMD" TP_SMD_Ø1.0mm 97.79,25.781 r0 top
TP45 "Ø1.0mm,SMD" TP_SMD_Ø1.0mm 97.79,27.686 r0 top
TP46 "Ø1.0mm,SMD" TP_SMD_Ø1.0mm 99.695,25.781 r0 top
TP47 "Ø1.0mm,SMD" TP_SMD_Ø1.0mm 99.695,27.686 r0 top
U1 "nRF52840-QIAA" AQFN50P700X700X85_HS-74N 115.164,37.617 r0 top locked
U2 "ATSAM3U2CA-AU" TSQFP50P1600X1600X160-100N 43.754,25.4 r90 top locked
U3 "MX25R6435F" SON127P600X80_HS-9N 113.919,23.673 r180 top locked
U4 "SC728CSTRT" BGA4C40P2X2_76X76X62 107.744,52.676 r180 top
U5 "FSA2466UMX" XQFN40P180X260X50-16N 73.939,19.71 r90 top
U6 "FSA2466UMX" XQFN40P180X260X50-16N 59.792,18.567 r180 top
U7 "FSA2466UMX" XQFN40P180X260X50-16N 81.94,19.71 r90 top locked
U8 "FSA2466UMX" XQFN40P180X260X50-16N 91.948,23.622 r180 top locked
U11 "XC9236" USP-6C 20.726,20.218 r0 top
U12 "XC9131" "10-USPB (2.9x2.6)" 12.344,26.264 r180 top
U13 "SC728CSTRT" BGA4C40P2X2_76X76X62 21.031,15.494 r0 top
U14 "SC728CSTRT" BGA4C40P2X2_76X76X62 21.031,13.843 r0 top
U15 "SC728CSTRT" BGA4C40P2X2_76X76X62 21.031,12.192 r0 top
U16 "SC728CSTRT" BGA4C40P2X2_76X76X62 25.578,17.882 r180 top
U17 "SC728CSTRT" BGA4C40P2X2_76X76X62 23.317,17.882 r180 top
U18 "SC728CSTRT" BGA4C40P2X2_76X76X62 30.119,17.186 r180 top
U19 "TS27L2IPT" TSOP65P640X120-8N 24.943,25.781 r0 top
U20 "74LVC1G08" SOT65P210X100-5N 24.968,14.605 r180 top
U21 "74LVC1G11" SOT65P210X100-6N 18.872,9.779 r0 top
U22 "TCK106AF" SOT95P280X140-5N 84.303,12.548 r270 top
U23 "TCK106AF" SOT95P280X140-5N 49.86,42.189 r180 top
U24 "SC728CSTRT" BGA4C40P2X2_76X76X62 27.483,30.353 r270 top
U25 "74LVC1G08" SOT65P210X100-5N 23.622,9.779 r0 top
X1 "32MHz" BT-XTAL_2016 119.425,43.713 r180 top
X2 "32.768kHz" XTAL_3215 108.671,38.525 r0 top
X20 "12MHz" BT-XTAL_3225 36.769,36.728 r180 top

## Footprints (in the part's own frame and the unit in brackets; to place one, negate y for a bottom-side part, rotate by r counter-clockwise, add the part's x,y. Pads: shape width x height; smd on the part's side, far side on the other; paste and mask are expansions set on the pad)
"10-USPB (2.9x2.6)" [mm] "PQFN, 10-Leads, Body 2.60x2.90mm, Pitch 0.50mm, Thermal Pad 1.60x2.50mm, IPC Medium Density"
  rect 0.45x0.475 smd paste-0.088 mask+0.07: 1(-1.27,1.15) 2(-1.27,0.5) 9(1.27,0.5) 10(1.27,1.15)
  rect 0.45x0.25 smd paste-0.05 mask+0.07: 3(-1.27,-0.15) 4(-1.27,-0.65) 5(-1.27,-1.15) 6(1.27,-1.15) 7(1.27,-0.65) 8(1.27,-0.15)
  rect 1.6x2.5 smd paste-5: 11(0,0)
  silkscreen extent -1.95,-1.53 1.35,2.1, body extent -1.3,-1.45 1.3,1.45, height 0.6
AQFN50P700X700X85_HS-74N [mm] "AQFN, 73-Leads, Body 7.00x7.00mm, Pitch 0.50mm, Thermal Pad 4.95x4.95mm, IPC Medium Density"
  rect 4.85x4.85 smd mask+0.05: 74(0,0)
  round 0.275 smd paste+0.012 mask+0.05: A8(-1.25,3.25) A10(-0.75,3.25) A12(-0.25,3.25) A14(0.25,3.25) A16(0.75,3.25) A18(1.25,3.25) A20(1.75,3.25) A22(2.25,3.25) A23(2.75,3.25) AA24(3.25,-2.25) AB2(-2.75,-2.5) AC5(-2,-2.75) AC9(-1,-2.75) AC11(-0.5,-2.75) AC13(0,-2.75) AC15(0.5,-2.75) AC17(1,-2.75) AC19(1.5,-2.75) AC21(2,-2.75) AC24(3.25,-2.75) AD2(-2.75,-3.25) AD4(-2.25,-3.25) AD6(-1.75,-3.25) AD8(-1.25,-3.25) AD10(-0.75,-3.25) AD12(-0.25,-3.25) AD14(0.25,-3.25) AD16(0.75,-3.25) AD18(1.25,-3.25) AD20(1.75,-3.25) AD22(2.25,-3.25) AD23(2.75,-3.25) B1(-3.25,2.75) B3(-2.5,2.75) B5(-2,2.75) B7(-1.5,2.75) B9(-1,2.75) B11(-0.5,2.75) B13(0,2.75) B15(0.5,2.75) B17(1,2.75) B19(1.5,2.75) B24(3.25,2.75) C1(-3.25,2.25) D2(-2.75,2) D23(2.75,2) E24(3.25,1.75) F2(-2.75,1.5) F23(2.75,1.5) G1(-3.25,1.25) H2(-2.75,1) H23(2.75,1) J1(-3.25,0.75) J24(3.25,0.75) K2(-2.75,0.5) L1(-3.25,0.25) L24(3.25,0.25) M2(-2.75,0) N1(-3.25,-0.25) N24(3.25,-0.25) P2(-2.75,-0.5) P23(2.75,-0.5) R1(-3.25,-0.75) R24(3.25,-0.75) T2(-2.75,-1) T23(2.75,-1) U1(-3.25,-1.25) U24(3.25,-1.25) V23(2.75,-1.5) W1(-3.25,-1.75) W24(3.25,-1.75) Y2(-2.75,-2) Y23(2.75,-2)
  silkscreen extent -4.56,-3.6 3.6,3.6, body extent -3.55,-3.55 3.55,3.55, height 0.85
BGA4C40P2X2_76X76X62 [mm] "BGA, 4-Leads, Body 0.8x0.8mm,  Pitch 0.40mm"
  round 0.22 smd mask+0.06: A1(-0.2,0.2) A2(0.2,0.2) B1(-0.2,-0.2) B2(0.2,-0.2)
  silkscreen extent -0.74,-0.45 0.45,0.74, body extent -0.38,-0.38 0.38,0.38, height 0.63
BT-XTAL_2016 [mm] "Crystal 2.0 x 1.6 mm"
  rect 0.95x0.85 smd: 1(-0.725,-0.575) 2(0.725,-0.575) 3(0.725,0.575) 4(-0.725,0.575)
  silkscreen extent -1.08,-0.88 1.08,0.88, body extent -1.05,-0.85 1.05,0.85, height 0.56
BT-XTAL_3225 [mm] "Mercury X32 series"
  rect 1.2x1.1 smd: 1(-1.194,-0.89) 2(1.194,-0.89) 3(1.194,0.891) 4(-1.194,0.891)
  silkscreen extent -1.8,-1.52 1.8,1.52, body extent -1.6,-1.25 1.6,1.25, height 0.6
CAPC1005X04L [mm] "Chip Capacitor, 2-Leads, Body 1.0x0.5mm, IPC High Density"
  rect 0.6x0.5 smd: 1(-0.5,0) 2(0.5,0)
  silkscreen extent -0.9,-0.35 0.9,0.35, body extent -0.51,-0.25 0.51,0.25, height 0.5
CAPC1608X06L [mm] "Chip Capacitor, 2-Leads, Body 1.6x0.8mm, IPC High Density"
  rect 0.75x0.8 smd: 1(-0.675,0) 2(0.675,0)
  silkscreen extent -1.17,-0.5 1.17,0.5, body extent -0.8,-0.43 0.8,0.43, height 0.8
CAPC2012X11L [mm] "Chip Capacitor, 2-Leads, Body 2.0x1.3mm, IPC High Density"
  rect 1.1x1.4 smd: 1(-0.75,0) 2(0.75,0)
  silkscreen extent -1.43,-0.8 1.42,0.8, body extent -1,-0.62 1,0.63, height 0.77
CAS-220TA [mm] "SLIDE SWITCH DPDT J HOOK"
  rect 1x1.6 smd: 1(-1.75,-1.85) 2(0,-1.85) 3(1.75,-1.85) 4(-1.75,1.85) 5(0,1.85) 6(1.75,1.85)
  silkscreen extent -2.8,-2.6 2.7,2, body extent -2.7,-2.15 2.7,2.16, height 2.51
CJS-120xA [mm] "Slide Switches - SPDT, SMD, ON-ON"
  rect 1x1.6 smd: 1(1.75,-1.15) 2(0,1.15) 3(-1.75,-1.15)
  silkscreen extent -3,-1.25 3,1.25, body extent -3,-1.4 3,1.45, height 2.5
COAXIAL-SWF [mm]
  rect 0.5x0.58 smd: 1(0,1.16) 3(0,-1.16)
  rect 0.75x0.8 smd: 2(-1.025,-0.95) 2(-1.025,0.95) 2(1.025,-0.95) 2(1.025,0.95)
  Top Layer pour cut-out: -0.65,0.55 0.65,0.55 0.65,1.35 -0.65,1.35
  Top Layer pour cut-out: 0.65,-0.55 -0.65,-0.55 -0.65,-1.35 0.65,-1.35
  silkscreen extent -1.25,-1.25 1.25,1.25, body extent -1.26,-1.3 1.26,1.3, height 1.55
CR2032_HOLDER_SMD [mm] "CR2032 - SMD mount coin cell bat holder"
  round 18 on Bottom Solder paste+0: 0(0,0)
  rect 5.08x5.08 smd: 1(-13.081,0) 1(13.081,0)
  rrect50% 10x10 smd paste-9: 2(0,0)
  Top Layer circle w5: c0,0 r6.5
  silkscreen extent -10.54,-9.53 10.54,11.43, body extent -15.37,-10.27 15.37,9.78, height 3.96
DFN65P100X40-3L [mm] "DFN, 3-Leads, Body 0.60x1.00mm, Pitch 0.65mm, IPC High Density"
  rect 0.4x0.25 smd: 1(-0.35,0.225) 2(-0.35,-0.225)
  rect 0.4x0.7 smd: 3(0.35,0)
  silkscreen extent -0.57,0.58 -0.48,0.67, body extent -0.53,-0.33 0.53,0.33, height 0.4
DO-216AA [mm]
  rect 0.762x1.27 smd: 1(1.65,0)
  rect 2.67x2.54 smd: 3(-0.7,0)
  silkscreen extent -1.6,-1.05 0.7,1.05, body extent -1.9,-1 1.95,1, height 1.01
Fiducial [mm] "Fiducial Mark"
  round 1 smd paste+0 mask+0.5: 0(0,0)
  round 1 smd far side paste+0 mask+0.5: 0(0,0)
  Top Layer keep-out circle w0.01: c0,0 r1
  Bottom Layer keep-out circle w0.01: c0,0 r1
FPC_05P-0.5mm-RA-SMD [mm] "FPC, 5-Leads, Pitch 0,5mm"
  rect 0.6x2.6 smd: 0(-0.9,-2.3) 0(2.9,-2.3)
  rect 0.3x0.8 smd: 1(0,0) 2(0.5,0) 3(1,0) 4(1.5,0) 5(2,0)
  silkscreen extent -1.45,-3.85 3.45,0, body extent -1.3,-3.85 3.3,0.2, height 1.2
HDR_2x3-SMD [mil] "Board-Board Conn, Header, 6-way, 2-row"
  rect 50x150 smd: 1(-100,-87.5) 2(-100,87.5) 3(0,-87.5) 4(0,87.5) 5(100,-87.5) 6(100,87.5)
  silkscreen extent -160,-140 150,100, body extent -150,-148 150,148, height 382
HDR_2x5-SMD-1.27mm-K [mm] "SMT MICRO HEADER, (1,27) .050\" Keying Shroud"
  rect 0.76x2.4 smd: 1(-2.54,-1.95) 2(-2.54,1.95) 3(-1.27,-1.95) 4(-1.27,1.95) 5(0,-1.95) 6(0,1.95) 7(1.27,-1.95) 8(1.27,1.95) 9(2.54,-1.95) 10(2.54,1.95)
  silkscreen extent -3.18,-3.15 3.18,3.15, body extent -3.14,-2.92 3.14,2.92, height 6.11
HDR_2x6-NC [mm] "Pin Header, 2.54mm through hole"
  rect 1.5x1.5 hole 0.9: 1(-6.35,-1.27)
  round 1.5 hole 0.9: 2(-6.35,1.27) 3(-3.81,-1.27) 4(-3.81,1.27) 5(-1.27,-1.27) 6(-1.27,1.27) 7(1.27,-1.27) 8(1.27,1.27) 9(3.81,-1.27) 10(3.81,1.27) 11(6.35,-1.27) 12(6.35,1.27)
  silkscreen extent -7.62,-2.54 7.62,2.54
HDR_2x8-NC [mm] "Pin Header, 2.54mm through hole"
  rect 1.5x1.5 hole 0.9: 1(-8.89,-1.27)
  round 1.5 hole 0.9: 2(-8.89,1.27) 3(-6.35,-1.27) 4(-6.35,1.27) 5(-3.81,-1.27) 6(-3.81,1.27) 7(-1.27,-1.27) 8(-1.27,1.27) 9(1.27,-1.27) 10(1.27,1.27) 11(3.81,-1.27) 12(3.81,1.27) 13(6.35,-1.27) 14(6.35,1.27) 15(8.89,-1.27) 16(8.89,1.27)
  silkscreen extent -10.16,-2.54 10.16,2.54
HDR_2x10-NC [mm] "Pin Header, 2.54mm through hole"
  rect 1.5x1.5 hole 0.9: 1(-11.43,-1.27)
  round 1.5 hole 0.9: 2(-11.43,1.27) 3(-8.89,-1.27) 4(-8.89,1.27) 5(-6.35,-1.27) 6(-6.35,1.27) 7(-3.81,-1.27) 8(-3.81,1.27) 9(-1.27,-1.27) 10(-1.27,1.27) 11(1.27,-1.27) 12(1.27,1.27) 13(3.81,-1.27) 14(3.81,1.27) 15(6.35,-1.27) 16(6.35,1.27) 17(8.89,-1.27) 18(8.89,1.27) 19(11.43,-1.27) 20(11.43,1.27)
  silkscreen extent -12.7,-2.54 12.7,2.54
HDR_2x10-SMD-1.27mm-NC [mm] "SMT MICRO HEADER, (1,27) .050\""
  rect 0.76x2.4 smd paste-5: 1(-5.715,-1.95) 2(-5.715,1.95) 3(-4.445,-1.95) 4(-4.445,1.95) 5(-3.175,-1.95) 6(-3.175,1.95) 7(-1.905,-1.95) 8(-1.905,1.95) 9(-0.635,-1.95) 10(-0.635,1.95) 11(0.635,-1.95) 12(0.635,1.95) 13(1.905,-1.95) 14(1.905,1.95) 15(3.175,-1.95) 16(3.175,1.95) 17(4.445,-1.95) 18(4.445,1.95) 19(5.715,-1.95) 20(5.715,1.95)
  silkscreen extent -6.35,-3.15 6.35,3.15
INDC1005X04L [mm] "Chip Inductor, 2-Leads, Body 1.0x0.5mm, IPC High Density"
  rect 0.65x0.5 smd: 1(-0.475,0) 2(0.475,0)
  silkscreen extent -0.9,-0.35 0.9,0.35, body extent -0.5,-0.3 0.5,0.3, height 0.5
INDC1608X06L [mm] "Chip Inductor, 2-Leads, Body 1.6x0.8mm, IPC High Density"
  rect 0.75x0.8 smd: 1(-0.675,0) 2(0.675,0)
  silkscreen extent -1.17,-0.5 1.17,0.5, body extent -0.8,-0.48 0.8,0.48, height 0.8
LED_0603_G [mil] "SMD Super Bright LED, GREEN"
  rect 30x32 smd: 1(-27.5,0) 2(27.5,0)
  silkscreen extent -58,-20 48,20, body extent -32,-16 32,16, height 24
LED_DUAL_0606 [mm]
  rect 0.65x0.85 smd paste+0: 1(0.425,0.725) 2(-0.425,0.725) 3(0.425,-0.725) 4(-0.425,-0.725)
  silkscreen extent -0.75,-0.8 0.75,0.8, body extent -0.75,-0.8 0.75,0.8, height 0.55
LIST_1x2-NC [mm] "Pin List, 2.54mm through hole"
  rect 1.5x1.5 hole 0.9: 1(-1.27,0)
  round 1.5 hole 0.9: 2(1.27,0)
  silkscreen extent -2.54,-1.27 2.54,1.27
LIST_1x3-NC [mm] "Pin List, 2.54mm through hole"
  rect 1.5x1.5 hole 0.9: 1(-2.54,0)
  round 1.5 hole 0.9: 2(0,0) 3(2.54,0)
  silkscreen extent -3.81,-1.27 3.81,1.27
LIST_1x6_SMD-NC [mm] "Pin List, 2.54mm, SMD"
  rect 1.02x2.19 smd paste+0: 1(0,-1.465) 1(0,1.465) 2(2.54,-1.465) 2(2.54,1.465) 3(5.08,-1.465) 3(5.08,1.465) 4(7.62,-1.465) 4(7.62,1.465) 5(10.16,-1.465) 5(10.16,1.465) 6(12.7,-1.465) 6(12.7,1.465)
  silkscreen extent -1.27,-1.27 13.97,1.27
LIST_1x8_SMD-NC [mm] "Pin List, 2.54mm, SMD"
  rect 1.02x2.19 smd paste+0: 1(0,-1.465) 1(0,1.465) 2(2.54,-1.465) 2(2.54,1.465) 3(5.08,-1.465) 3(5.08,1.465) 4(7.62,-1.465) 4(7.62,1.465) 5(10.16,-1.465) 5(10.16,1.465) 6(12.7,-1.465) 6(12.7,1.465) 7(15.24,-1.465) 7(15.24,1.465) 8(17.78,-1.465) 8(17.78,1.465)
  silkscreen extent -1.27,-1.27 19.05,1.27
LIST_1x10_SMD-NC [mm] "Pin List, 2.54mm, SMD"
  rect 1.02x2.19 smd paste+0: 1(0,-1.465) 1(0,1.465) 2(2.54,-1.465) 2(2.54,1.465) 3(5.08,-1.465) 3(5.08,1.465) 4(7.62,-1.465) 4(7.62,1.465) 5(10.16,-1.465) 5(10.16,1.465) 6(12.7,-1.465) 6(12.7,1.465) 7(15.24,-1.465) 7(15.24,1.465) 8(17.78,-1.465) 8(17.78,1.465) 9(20.32,-1.465) 9(20.32,1.465) 10(22.86,-1.465) 10(22.86,1.465)
  silkscreen extent -1.27,-1.27 24.13,1.27
LIST_1x12_SMD [mm] "Pin List, 2.54mm, SMD"
  rect 1.02x2.19 smd: 1(0,-1.465) 1(0,1.465) 2(2.54,-1.465) 2(2.54,1.465) 3(5.08,-1.465) 3(5.08,1.465) 4(7.62,-1.465) 4(7.62,1.465) 5(10.16,-1.465) 5(10.16,1.465) 6(12.7,-1.465) 6(12.7,1.465) 7(15.24,-1.465) 7(15.24,1.465) 8(17.78,-1.465) 8(17.78,1.465) 9(20.32,-1.465) 9(20.32,1.465) 10(22.86,-1.465) 10(22.86,1.465) 11(25.4,-1.465) 11(25.4,1.465) 12(27.94,-1.465) 12(27.94,1.465)
  silkscreen extent -1.27,-1.27 29.21,1.27, body extent -1.27,-2.5 29.21,2.5, height 9.82
LIST_1x12_SMD-NC [mm] "Pin List, 2.54mm, SMD"
  rect 1.02x2.19 smd paste+0: 1(0,-1.465) 1(0,1.465) 2(2.54,-1.465) 2(2.54,1.465) 3(5.08,-1.465) 3(5.08,1.465) 4(7.62,-1.465) 4(7.62,1.465) 5(10.16,-1.465) 5(10.16,1.465) 6(12.7,-1.465) 6(12.7,1.465) 7(15.24,-1.465) 7(15.24,1.465) 8(17.78,-1.465) 8(17.78,1.465) 9(20.32,-1.465) 9(20.32,1.465) 10(22.86,-1.465) 10(22.86,1.465) 11(25.4,-1.465) 11(25.4,1.465) 12(27.94,-1.465) 12(27.94,1.465)
  silkscreen extent -1.27,-1.27 29.21,1.27
LIST_ANG_1x2-SMD-2.54MM [mm] "Pin List, 2.54mm, Surface Mount, Angled"
  round 1.78 hole 1.78 unplated: 0(0,-4.496)
  rect 1.27x3.18 smd: 1(-1.27,0) 2(1.27,0)
  silkscreen extent -2.54,-11.58 2.54,-1.8, body extent -2.56,-11.61 2.52,1.35, height 3.03
MKH-22D14-G2-B [mm] "Slide Switches - DPDT, SMD, ON-ON"
  rect 1.2x2 smd: 1(2.5,-2.75) 2(0,-2.75) 3(-2.5,-2.75) 4(2.5,2.75) 5(0,2.75) 6(-2.5,2.75)
  silkscreen extent -4.5,-3.75 4.5,1.75, body extent -4.25,-3.75 4.25,2.5, height 3.5
RESC1005X04L [mm] "Chip Resistor, 2-Leads, Body 1.0x0.5mm, IPC High Density"
  rect 0.6x0.55 smd: 1(-0.5,0) 2(0.5,0)
  silkscreen extent -0.87,-0.38 0.88,0.38, body extent -0.5,-0.25 0.5,0.25, height 0.3
SM02B-SRSS-TB [mm] "JST, SH connector, side entry SMD, 1mm pitch"
  rect 1.2x1.8 smd: 0(-2.1,-3.875) 0(2.1,-3.875)
  rect 0.6x1.55 smd: 1(-0.5,0) 2(0.5,0)
  silkscreen extent -2,-4.57 2,-0.33, body extent -1.99,-4.58 1.99,0.41, height 3
SOCKET_1x6_SMD [mm] "Socket, 2.54mm, SMD"
  rect 1.02x2.19 smd: 1(0,-1.465) 1(0,1.465) 2(2.54,-1.465) 2(2.54,1.465) 3(5.08,-1.465) 3(5.08,1.465) 4(7.62,-1.465) 4(7.62,1.465) 5(10.16,-1.465) 5(10.16,1.465) 6(12.7,1.465) 6(12.7,-1.465)
  silkscreen extent -1.27,-1.27 13.97,1.27, body extent -1.27,-2.29 13.97,2.29, height 7.47
SOCKET_1x8_SMD [mm] "Socket, 2.54mm, SMD"
  rect 1.02x2.19 smd: 1(0,-1.465) 1(0,1.465) 2(2.54,-1.465) 2(2.54,1.465) 3(5.08,-1.465) 3(5.08,1.465) 4(7.62,-1.465) 4(7.62,1.465) 5(10.16,-1.465) 5(10.16,1.465) 6(12.7,1.465) 6(12.7,-1.465) 7(15.24,-1.465) 7(15.24,1.465) 8(17.78,-1.465) 8(17.78,1.465)
  silkscreen extent -1.27,-1.27 19.05,1.27, body extent -1.27,-2.29 19.05,2.29, height 7.47
SOCKET_1x10_SMD [mm] "Socket, 2.54mm, SMD"
  rect 1.02x2.19 smd: 1(0,1.465) 1(0,-1.465) 2(2.54,-1.465) 2(2.54,1.465) 3(5.08,-1.465) 3(5.08,1.465) 4(7.62,-1.465) 4(7.62,1.465) 5(10.16,-1.465) 5(10.16,1.465) 6(12.7,-1.465) 6(12.7,1.465) 7(15.24,-1.465) 7(15.24,1.465) 8(17.78,-1.465) 8(17.78,1.465) 9(20.32,-1.465) 9(20.32,1.465) 10(22.86,-1.465) 10(22.86,1.465)
  silkscreen extent -1.27,-1.27 24.13,1.27, body extent -1.27,-2.29 24.13,2.29, height 7.47
SOCKET_2x3_SMD-2.54mm-bottom-NC [mm] "Socket, 2.54mm, SMD"
  rect 1.02x2.22 smd far side: 1(-2.54,-2.825) 2(-2.54,2.825) 3(0,-2.825) 4(0,2.825) 5(2.54,-2.825) 6(2.54,2.825)
SOCKET_2x9_SMD-2.54mm [mil] "CONN HEADER VERT DUAL 18POS SMD - FEMALE HEADER, PCB, 0.1\", 10+10WAY"
  rect 50x150 smd: 1(-400,-87.5) 2(-400,87.5) 3(-300,-87.5) 4(-300,87.5) 5(-200,-87.5) 6(-200,87.5) 7(-100,-87.5) 8(-100,87.5) 9(0,-87.5) 10(0,87.5) 11(100,-87.5) 12(100,87.5) 13(200,-87.5) 14(200,87.5) 15(300,-87.5) 16(300,87.5) 17(400,-87.5) 18(400,87.5)
  silkscreen extent -460,-140 450,100, body extent -450,-138 450,139, height 290
SODFL100X40-2N [mm] "SODFL, 2-Leads, Body 0.60x1.00mm, IPC Medium Density"
  rect 0.36x0.25 smd: 1(-0.42,0) 2(0.42,0)
  silkscreen extent -0.7,-0.35 0.5,0.5, body extent -0.5,-0.33 0.5,0.33, height 0.4
Solderbridge#1 [mm]
  round 0.2 smd paste-10: 1(-0.312,0) 2(0.312,0)
  Top Layer region: -0.077,-0.432 -0.152,-0.505 -0.271,-0.467 -0.335,-0.424 -0.409,-0.351 -0.462,-0.292 -0.521,-0.193 -0.549,-0.099 -0.544,0.122 -0.518,0.193 -0.434,0.33 -0.351,0.411 -0.259,0.469 -0.157,0.5 -0.107,0.483 -0.077,0.43
  Top Layer region: 0.077,0.432 0.152,0.505 0.271,0.467 0.335,0.424 0.409,0.351 0.462,0.292 0.521,0.193 0.549,0.099 0.544,-0.122 0.518,-0.193 0.434,-0.33 0.351,-0.411 0.259,-0.469 0.157,-0.5 0.107,-0.483 0.077,-0.43
  Top Layer lines w0.152: -0.153,0.431 ccw(c-0.042,0) -0.153,-0.431 ; 0.153,0.431 cw(c0.042,0) 0.487,0 cw(c0.042,0) 0.461,-0.149 cw(c0.042,0) 0.153,-0.431
Solderbridge#2 [mm]
  round 0.2 smd paste-10: 1(-0.312,0) 2(0.312,0)
  Top Layer region: -0.077,-0.432 -0.152,-0.505 -0.271,-0.467 -0.335,-0.424 -0.409,-0.351 -0.462,-0.292 -0.521,-0.193 -0.549,-0.099 -0.544,0.122 -0.518,0.193 -0.434,0.33 -0.351,0.411 -0.259,0.469 -0.157,0.5 -0.107,0.483 -0.077,0.43
  Top Layer region: 0.077,0.432 0.152,0.505 0.271,0.467 0.335,0.424 0.409,0.351 0.462,0.292 0.521,0.193 0.549,0.099 0.544,-0.122 0.518,-0.193 0.434,-0.33 0.351,-0.411 0.259,-0.469 0.157,-0.5 0.107,-0.483 0.077,-0.43
  Top Layer lines w0.152: -0.153,0.431 ccw(c-0.042,0) -0.153,-0.431 ; 0.153,0.431 cw(c0.042,0) 0.153,-0.431
Solderbridge#3 [mm]
  round 0.2 smd paste-10: 1(-0.312,0) 2(0.312,0)
  Top Layer region: -0.077,-0.432 -0.152,-0.505 -0.271,-0.467 -0.335,-0.424 -0.409,-0.351 -0.462,-0.292 -0.521,-0.193 -0.549,-0.099 -0.544,0.122 -0.518,0.193 -0.434,0.33 -0.351,0.411 -0.259,0.469 -0.157,0.5 -0.107,0.483 -0.077,0.43
  Top Layer region: 0.077,0.432 0.152,0.505 0.271,0.467 0.335,0.424 0.409,0.351 0.462,0.292 0.521,0.193 0.549,0.099 0.544,-0.122 0.518,-0.193 0.434,-0.33 0.351,-0.411 0.259,-0.469 0.157,-0.5 0.107,-0.483 0.077,-0.43
  Top Layer lines w0.152: -0.153,-0.431 cw(c-0.042,0) -0.153,0.431 ; 0.153,-0.431 ccw(c0.042,0) 0.487,0 ccw(c0.042,0) 0.153,0.431
Solderbridge#4 [mm]
  round 0.2 smd paste-10: 1(-0.312,0) 2(0.312,0)
  Top Layer region: -0.077,-0.432 -0.152,-0.505 -0.271,-0.467 -0.335,-0.424 -0.409,-0.351 -0.462,-0.292 -0.521,-0.193 -0.549,-0.099 -0.544,0.122 -0.518,0.193 -0.434,0.33 -0.351,0.411 -0.259,0.469 -0.157,0.5 -0.107,0.483 -0.077,0.43
  Top Layer region: 0.077,0.432 0.152,0.505 0.271,0.467 0.335,0.424 0.409,0.351 0.462,0.292 0.521,0.193 0.549,0.099 0.544,-0.122 0.518,-0.193 0.434,-0.33 0.351,-0.411 0.259,-0.469 0.157,-0.5 0.107,-0.483 0.077,-0.43
  Top Layer lines w0.152: 0.153,-0.431 ccw(c0.042,0) 0.302,-0.361 ccw(c0.042,0) 0.302,0.361 ccw(c0.042,0) 0.153,0.431 ; -0.153,-0.431 cw(c-0.042,0) -0.48,0.079 cw(c-0.042,0) -0.153,0.431
Solderbridge_Shorted#1 [mm]
  round 0.2 smd paste-10: 1(-0.338,0) 2(0.338,0)
  Top Layer region: 0.102,0.432 0.178,0.505 0.296,0.467 0.361,0.424 0.434,0.351 0.488,0.292 0.546,0.193 0.574,0.099 0.569,-0.122 0.544,-0.193 0.46,-0.33 0.376,-0.411 0.284,-0.469 0.183,-0.5 0.132,-0.483 0.102,-0.43
  Top Layer region: -0.102,-0.432 -0.178,-0.505 -0.296,-0.467 -0.361,-0.424 -0.434,-0.351 -0.488,-0.292 -0.546,-0.193 -0.574,-0.099 -0.569,0.122 -0.544,0.193 -0.46,0.33 -0.376,0.411 -0.284,0.469 -0.183,0.5 -0.132,0.483 -0.102,0.43
  Top Layer lines w0.152: -0.178,0.431 ccw(c-0.068,0) -0.178,-0.431 ; 0.178,0.431 cw(c0.068,0) 0.178,-0.431
  Top Layer lines w0.203: -0.338,0 0.338,0
Solderbridge_Shorted#2 [mm]
  round 0.2 smd paste-10: 1(-0.338,0) 2(0.338,0)
  Top Layer region: 0.102,0.432 0.178,0.505 0.296,0.467 0.361,0.424 0.434,0.351 0.488,0.292 0.546,0.193 0.574,0.099 0.569,-0.122 0.544,-0.193 0.46,-0.33 0.376,-0.411 0.284,-0.469 0.183,-0.5 0.132,-0.483 0.102,-0.43
  Top Layer region: -0.102,-0.432 -0.178,-0.505 -0.296,-0.467 -0.361,-0.424 -0.434,-0.351 -0.488,-0.292 -0.546,-0.193 -0.574,-0.099 -0.569,0.122 -0.544,0.193 -0.46,0.33 -0.376,0.411 -0.284,0.469 -0.183,0.5 -0.132,0.483 -0.102,0.43
  Top Layer lines w0.152: -0.178,-0.431 cw(c-0.068,0) -0.512,0 cw(c-0.068,0) -0.178,0.431 ; 0.178,-0.431 ccw(c0.068,0) 0.178,0.431
  Top Layer lines w0.203: -0.338,0 0.338,0
SON127P600X80_HS-9N [mm] "SON, 8-Leads, Body 5.00x6.00mm, Pitch 1.27mm, Thermal Pad 4.00x3.40mm, IPC Medium Density"
  rect 1.15x0.45 smd: 1(-2.77,1.905) 2(-2.77,0.635) 3(-2.77,-0.635) 4(-2.77,-1.905) 5(2.77,-1.905) 6(2.77,-0.635) 7(2.77,0.635) 8(2.77,1.905)
  rect 3.4x4 smd paste-1.7: 9(0,0)
  silkscreen extent -3.98,-2.6 3.1,2.67, body extent -3.05,-2.55 3.05,2.55, height 0.8
SOT65P210X100-5N [mm] "SOT23, 5-Leads, Body 2,2x2,4mm (max), Pitch 0,65mm, IPC Medium Density"
  rect 0.9x0.35 smd: 1(-0.95,0.65) 2(-0.95,0) 3(-0.95,-0.65) 4(0.95,-0.65) 5(0.95,0.65)
  silkscreen extent -1.08,-1.1 0.1,1.5, body extent -1.1,-1 1.1,1, height 0.97
SOT65P210X100-6N [mm] "SOT23, 6-Leads, Body 2,2x2,4mm (max), Pitch 0,65mm, IPC Medium Density"
  rect 0.9x0.35 smd: 1(-0.95,0.65) 2(-0.95,0) 3(-0.95,-0.65) 4(0.95,-0.65) 5(0.95,0) 6(0.95,0.65)
  silkscreen extent -1.08,-1.1 0.1,1.5, body extent -1.05,-1 1.05,1, height 0.92
SOT89-150P409X160-3N [mm] "SOT89, 3-Leads, Body 4.50x2.45mm, Pitch 1.50mm, Lead Span 4.1mm, IPC Medium Density"
  rect 1.4x0.6 smd: 1(-1.8,1.5) 3(-1.8,-1.5)
  rect 1.7x0.6 smd: 2(-1.65,0)
  Top Layer region: -0.8,0.3 -0.15,0.95 1.85,0.95 2.5,0.3 2.5,-0.3 1.85,-0.95 -0.15,-0.95 -0.8,-0.3
  silkscreen extent -2.05,-2.3 1.32,2.47, body extent -2.2,-2.3 1.93,2.3, height 1.6
SOT95P280X140-5N [mm] "SOT23, 5-Leads, Body 2,90x2,80mm, Pitch 0,95mm, IPC Medium Density"
  rect 1x0.6 smd: 1(-1.35,0.95) 2(-1.35,0) 3(-1.35,-0.95) 4(1.35,-0.95) 5(1.35,0.95)
  silkscreen extent -1.47,-1.5 0.45,1.93, body extent -1.5,-1.55 1.5,1.55, height 1.4
SOT190P230X110-4L [mm] "SOT143, 4-Leads, Body 3.0x2.5mm (max), Pitch 1.90mm, IPC High Density"
  rect 0.85x1 smd: 1(-1.025,0.75)
  rect 0.85x0.6 smd: 2(-1.025,-0.95) 3(1.025,-0.95) 4(1.025,0.95)
  silkscreen extent -1.15,-1.5 0.7,1.92, body extent -1.21,-1.46 1.21,1.46, height 1
Switch-PB-6.2x6.3mm-SMD [mm] "6.2×6.5mm TACT Switch, without ground connector"
  rect 2.75x1.4 smd: 1(-3.375,2) 1(3.375,2) 2(-3.375,-2) 2(3.375,-2)
  silkscreen extent -3,-3 3,3, body extent -4,-3 4,3.3, height 3.1
Switch-Slide-J-Lead-DP3T-13x3.5mm [mm] "Slide Switch - DP3T, SMD, ON-ON-ON"
  rect 1.2x1.6 smd: 1(-4,-1.4) 2(-2,-1.4) 3(2,-1.4) 4(4,-1.4) 5(-4,1.4) 6(-2,1.4) 7(2,1.4) 8(4,1.4)
  silkscreen extent -6,-1.75 6,1.75, body extent -6,-1.8 6,1.7, height 5.5
TC2050-IDC-NLFP [mil]
  round 39 hole 39 unplated: 0(-150,0) 0(150,-40) 0(150,40)
  round 31 smd paste-196.85: 1(-100,-25) 2(-50,-25) 3(0,-25) 4(50,-25) 5(100,-25) 6(100,25) 7(50,25) 8(0,25) 9(-50,25) 10(-100,25)
  Top Layer pour cut-out: -100,25 -100,-25 100,-25 100,25
TESTPAD-TH [mm]
  round 1.5 hole 1: 1(0,0)
  silkscreen extent -1,-1 1,1
TP_SMD_Ø1.0mm [mm]
  round 1 smd paste-5: 1(0,0)
  silkscreen extent -0.7,-0.7 0.7,0.7
TP_SMD_Ø1.5mm [mm]
  round 1.5 smd paste-5: 1(0,0)
  silkscreen extent -0.95,-0.95 0.95,0.95
TSOP65P640X120-8N [mm] "TSOP, 8-Leads, Body 3.00x4.40mm, Pitch 0.65mm, IPC Medium Density"
  oval 1.4x0.45 smd: 1(-2.95,0.975) 2(-2.95,0.325) 3(-2.95,-0.325) 4(-2.95,-0.975) 5(2.95,-0.975) 6(2.95,-0.325) 7(2.95,0.325) 8(2.95,0.975)
  silkscreen extent -3.07,-1.55 1.85,1.87, body extent -3.2,-1.55 3.2,1.55, height 1.2
TSQFP50P1600X1600X160-100N [mm] "TSQFP, 100-Leads, Body 16,0x16,0mm (max), Pitch 0,50mm, IPC Medium Density"
  oval 1.65x0.3 smd: 1(-7.575,6) 2(-7.575,5.5) 3(-7.575,5) 4(-7.575,4.5) 5(-7.575,4) 6(-7.575,3.5) 7(-7.575,3) 8(-7.575,2.5) 9(-7.575,2) 10(-7.575,1.5) 11(-7.575,1) 12(-7.575,0.5) 13(-7.575,0) 14(-7.575,-0.5) 15(-7.575,-1) 16(-7.575,-1.5) 17(-7.575,-2) 18(-7.575,-2.5) 19(-7.575,-3) 20(-7.575,-3.5) 21(-7.575,-4) 22(-7.575,-4.5) 23(-7.575,-5) 24(-7.575,-5.5) 25(-7.575,-6) 51(7.575,-6) 52(7.575,-5.5) 53(7.575,-5) 54(7.575,-4.5) 55(7.575,-4) 56(7.575,-3.5) 57(7.575,-3) 58(7.575,-2.5) 59(7.575,-2) 60(7.575,-1.5) 61(7.575,-1) 62(7.575,-0.5) 63(7.575,0) 64(7.575,0.5) 65(7.575,1) 66(7.575,1.5) 67(7.575,2) 68(7.575,2.5) 69(7.575,3) 70(7.575,3.5) 71(7.575,4) 72(7.575,4.5) 73(7.575,5) 74(7.575,5.5) 75(7.575,6)
  oval 0.3x1.65 smd: 26(-6,-7.575) 27(-5.5,-7.575) 28(-5,-7.575) 29(-4.5,-7.575) 30(-4,-7.575) 31(-3.5,-7.575) 32(-3,-7.575) 33(-2.5,-7.575) 34(-2,-7.575) 35(-1.5,-7.575) 36(-1,-7.575) 37(-0.5,-7.575) 38(0,-7.575) 39(0.5,-7.575) 40(1,-7.575) 41(1.5,-7.575) 42(2,-7.575) 43(2.5,-7.575) 44(3,-7.575) 45(3.5,-7.575) 46(4,-7.575) 47(4.5,-7.575) 48(5,-7.575) 49(5.5,-7.575) 50(6,-7.575) 76(6,7.575) 77(5.5,7.575) 78(5,7.575) 79(4.5,7.575) 80(4,7.575) 81(3.5,7.575) 82(3,7.575) 83(2.5,7.575) 84(2,7.575) 85(1.5,7.575) 86(1,7.575) 87(0.5,7.575) 88(0,7.575) 89(-0.5,7.575) 90(-1,7.575) 91(-1.5,7.575) 92(-2,7.575) 93(-2.5,7.575) 94(-3,7.575) 95(-3.5,7.575) 96(-4,7.575) 97(-4.5,7.575) 98(-5,7.575) 99(-5.5,7.575) 100(-6,7.575)
  silkscreen extent -7.7,-6.35 6.35,6.82, body extent -8,-8 8,8, height 1.6
TY-NR3015 [mm] "Molded Inductor, 2-Leads, Body 3.00x3.00mm, IPC Medium Density"
  rect 0.8x2.7 smd: 1(-1.1,0) 2(1.1,0)
  silkscreen extent -2.05,-1.55 1.55,1.75, body extent -1.5,-1.5 1.5,1.5, height 1.35
USB-Micro-B-RA-SMD-PiP [mm] "Micro USB B SMT"
  rect 1.35x0.4 smd: 1(0,1.3) 2(0,0.65) 3(0,0) 4(0,-0.65) 5(0,-1.3)
  oval 1.6x0.9 hole 0.5 slot 1.2 at 0 deg: 6(-2.675,-3.3) 6(-2.675,3.3)
  oval 2x1.5 on Top Paste: 6(-2.675,-3.3) 6(-2.675,3.3)
  rect 1.55x1.9 smd: 6(-2.675,-1.2) 6(-2.675,1.2)
  rect 1.4x1.6 smd: 6(-0.225,-3.2) 6(-0.225,3.2)
  silkscreen extent -4.75,-3.75 0.25,3.75, body extent -5.28,-4.1 0.15,4.1, height 2.72
USP-6C [mm] "DFN, 6-Leads, Body 2.00x1.80mm, Pitch 0.50mm, Thermal Pad 1.00x1.40mm, IPC Medium Density"
  rect 0.45x0.35 smd paste-0.05: 1(-0.975,0.55)
  rect 0.45x0.25 smd paste-0.05: 2(-0.975,0) 3(-0.975,-0.5) 4(0.975,-0.5) 5(0.975,0) 6(0.975,0.5)
  rect 0.9x1.8 smd paste-2: 7(0,0)
  Top Layer region: -0.5,-0.8 0.5,-0.8 0.5,0.8 -0.5,0.8
  silkscreen extent -1.42,-1.07 0.97,1.12, body extent -0.93,-1.02 0.93,1.02, height 0.6
XQFN40P180X260X50-16N [mm] "QFN, 16-Leads, Body 1.80x2.60mm, Pitch 0.40mm, IPC Medium Density"
  oval 0.65x0.22 smd paste-0.02 mask+0.062: 1(-0.825,0.6) 2(-0.825,0.2) 3(-0.825,-0.2) 4(-0.825,-0.6) 9(0.825,-0.6) 10(0.825,-0.2) 11(0.825,0.2) 12(0.825,0.6)
  oval 0.22x0.65 smd paste-0.02 mask+0.062: 5(-0.6,-1.225) 6(-0.2,-1.225) 7(0.2,-1.225) 8(0.6,-1.225) 13(0.6,1.225) 14(0.2,1.225) 15(-0.2,1.225) 16(-0.6,1.225)
  silkscreen extent -1.45,-1.4 1,1.4, body extent -0.91,-1.31 0.91,1.31, height 0.55
XTAL_3215 [mm] "XTAL SMD 3.2 x 1.5 mm"
  rect 1x1.8 smd: 1(-1.25,0) 2(1.25,0)
  silkscreen extent -0.6,-0.75 0.6,0.75, body extent -1.6,-0.75 1.6,0.75, height 0.81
